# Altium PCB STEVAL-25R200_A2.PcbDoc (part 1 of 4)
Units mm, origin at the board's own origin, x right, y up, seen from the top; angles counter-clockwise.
Board outline 84.5 x 100 mm, 4 copper layers (Top Layer, F2, F3, Bottom Layer), stack 0.78 mm thick; 272 components, 152 nets, 679 pads, 380 vias.
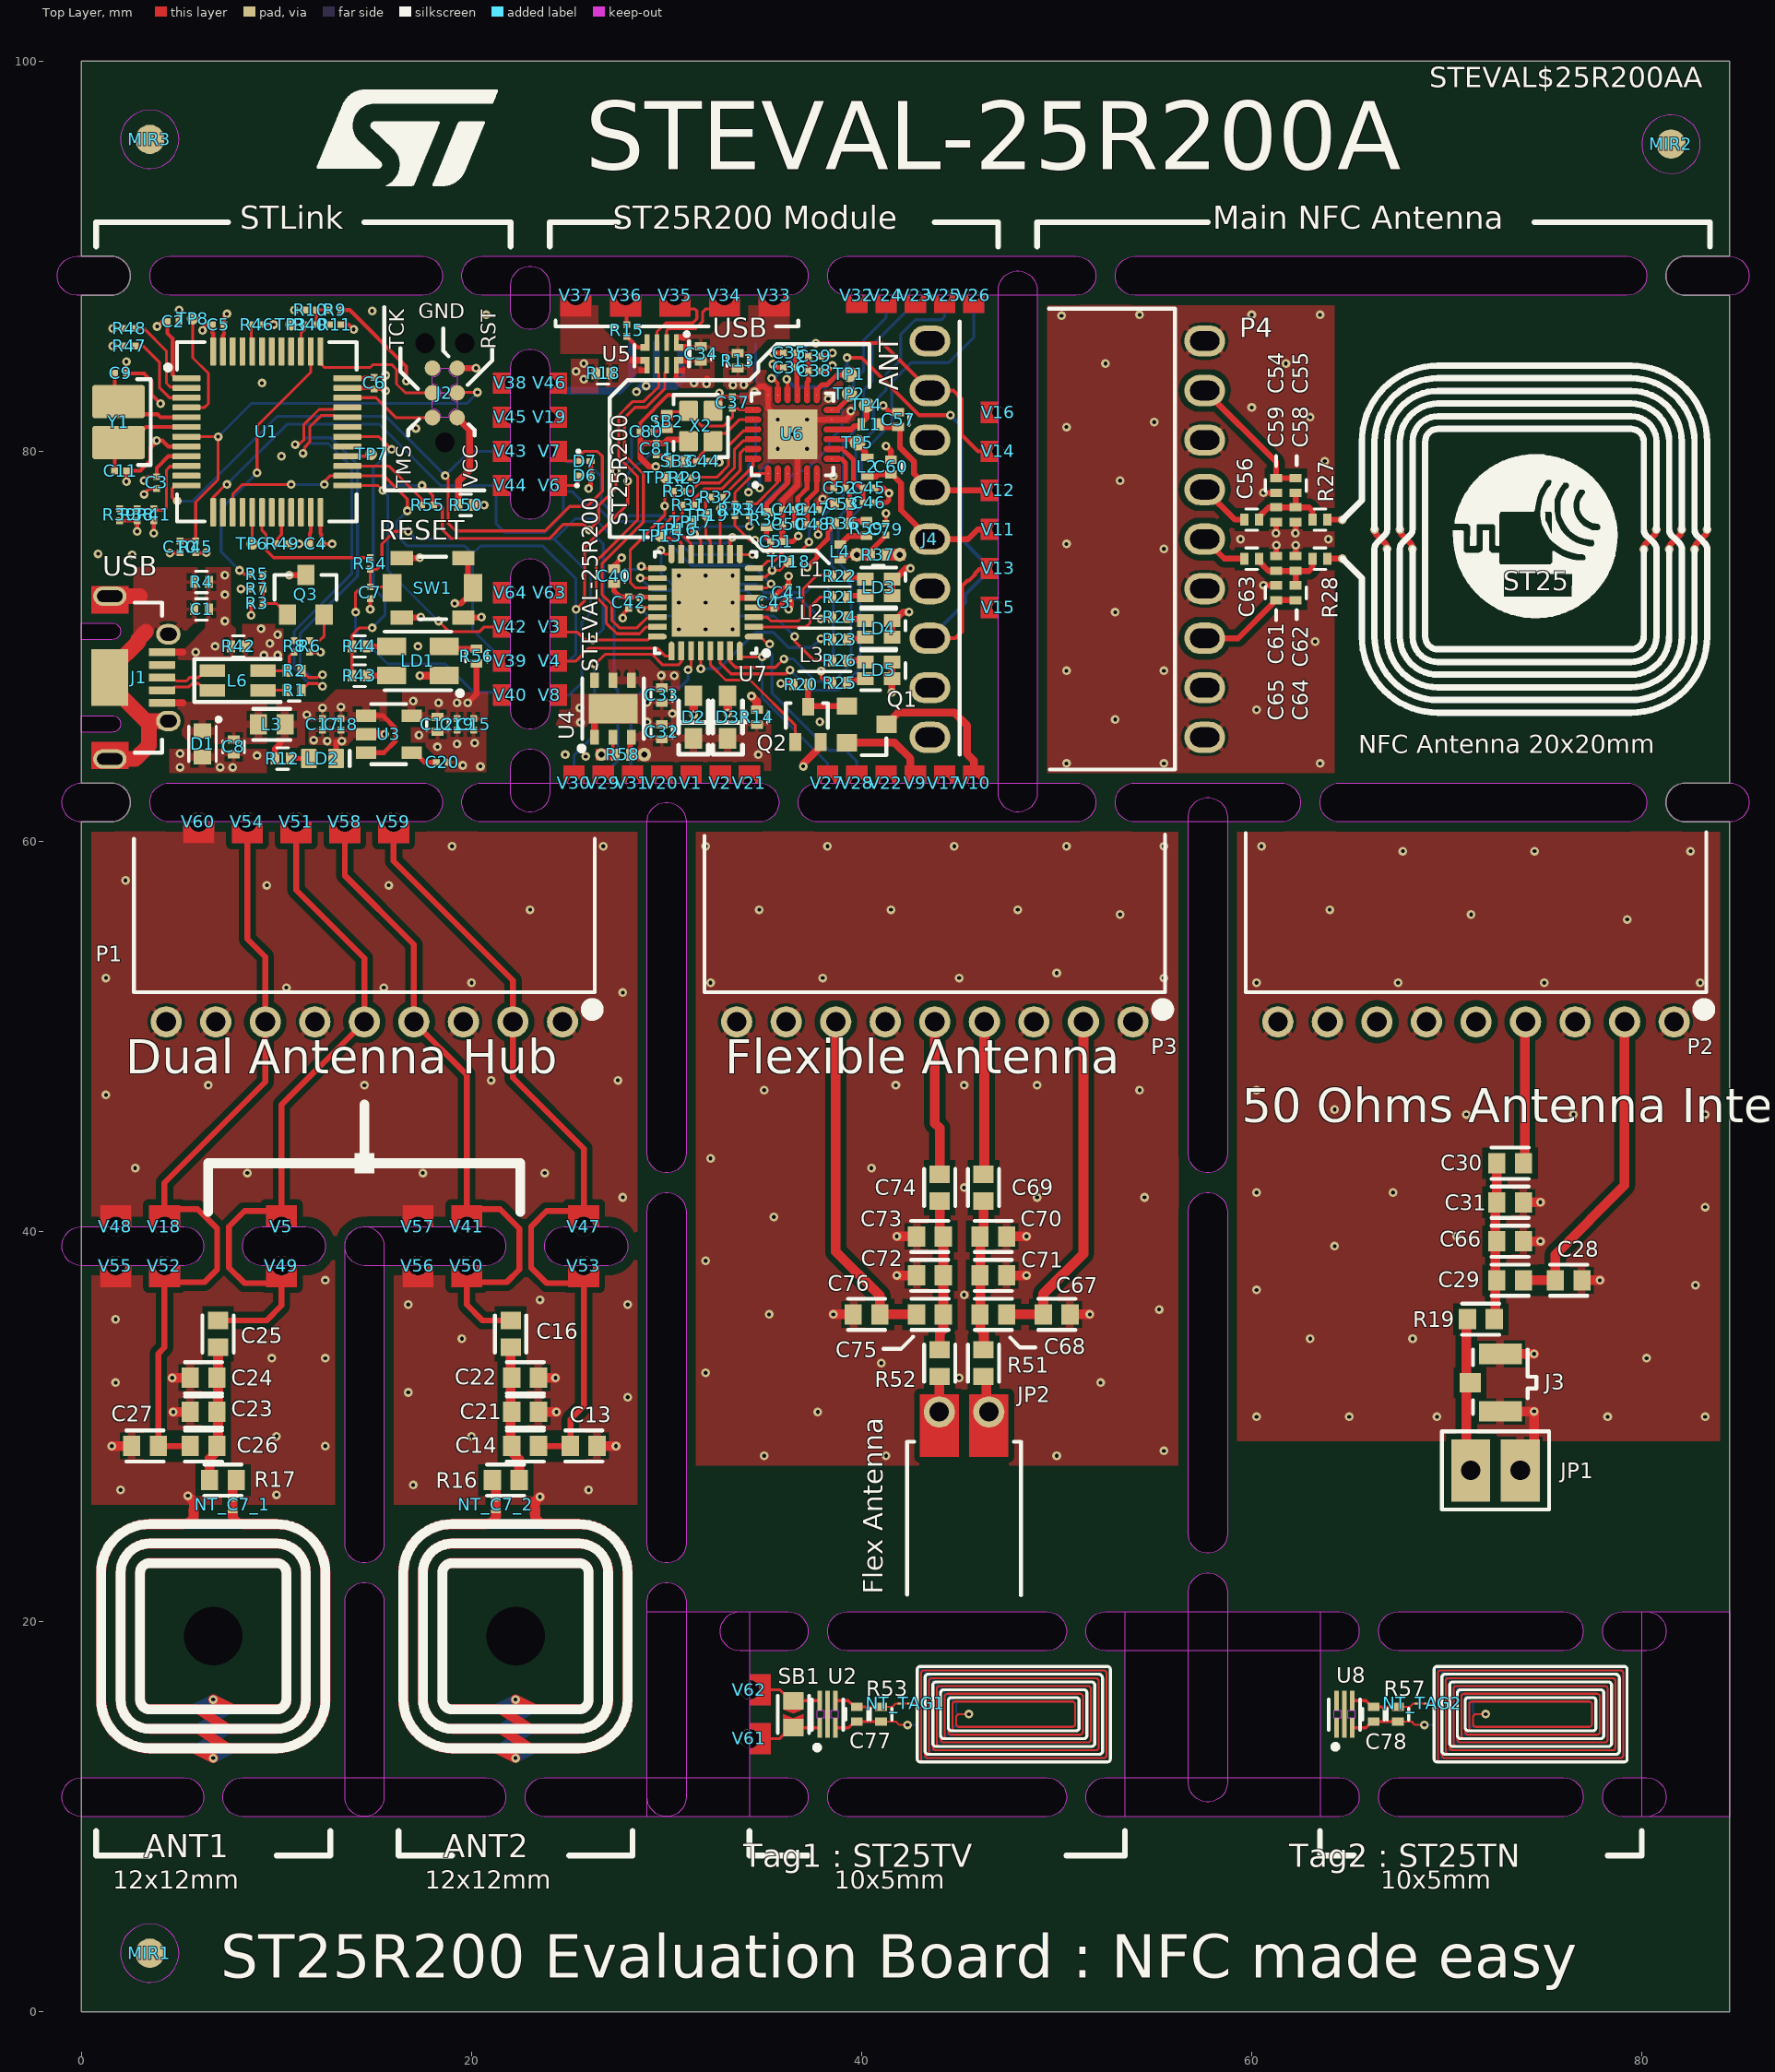
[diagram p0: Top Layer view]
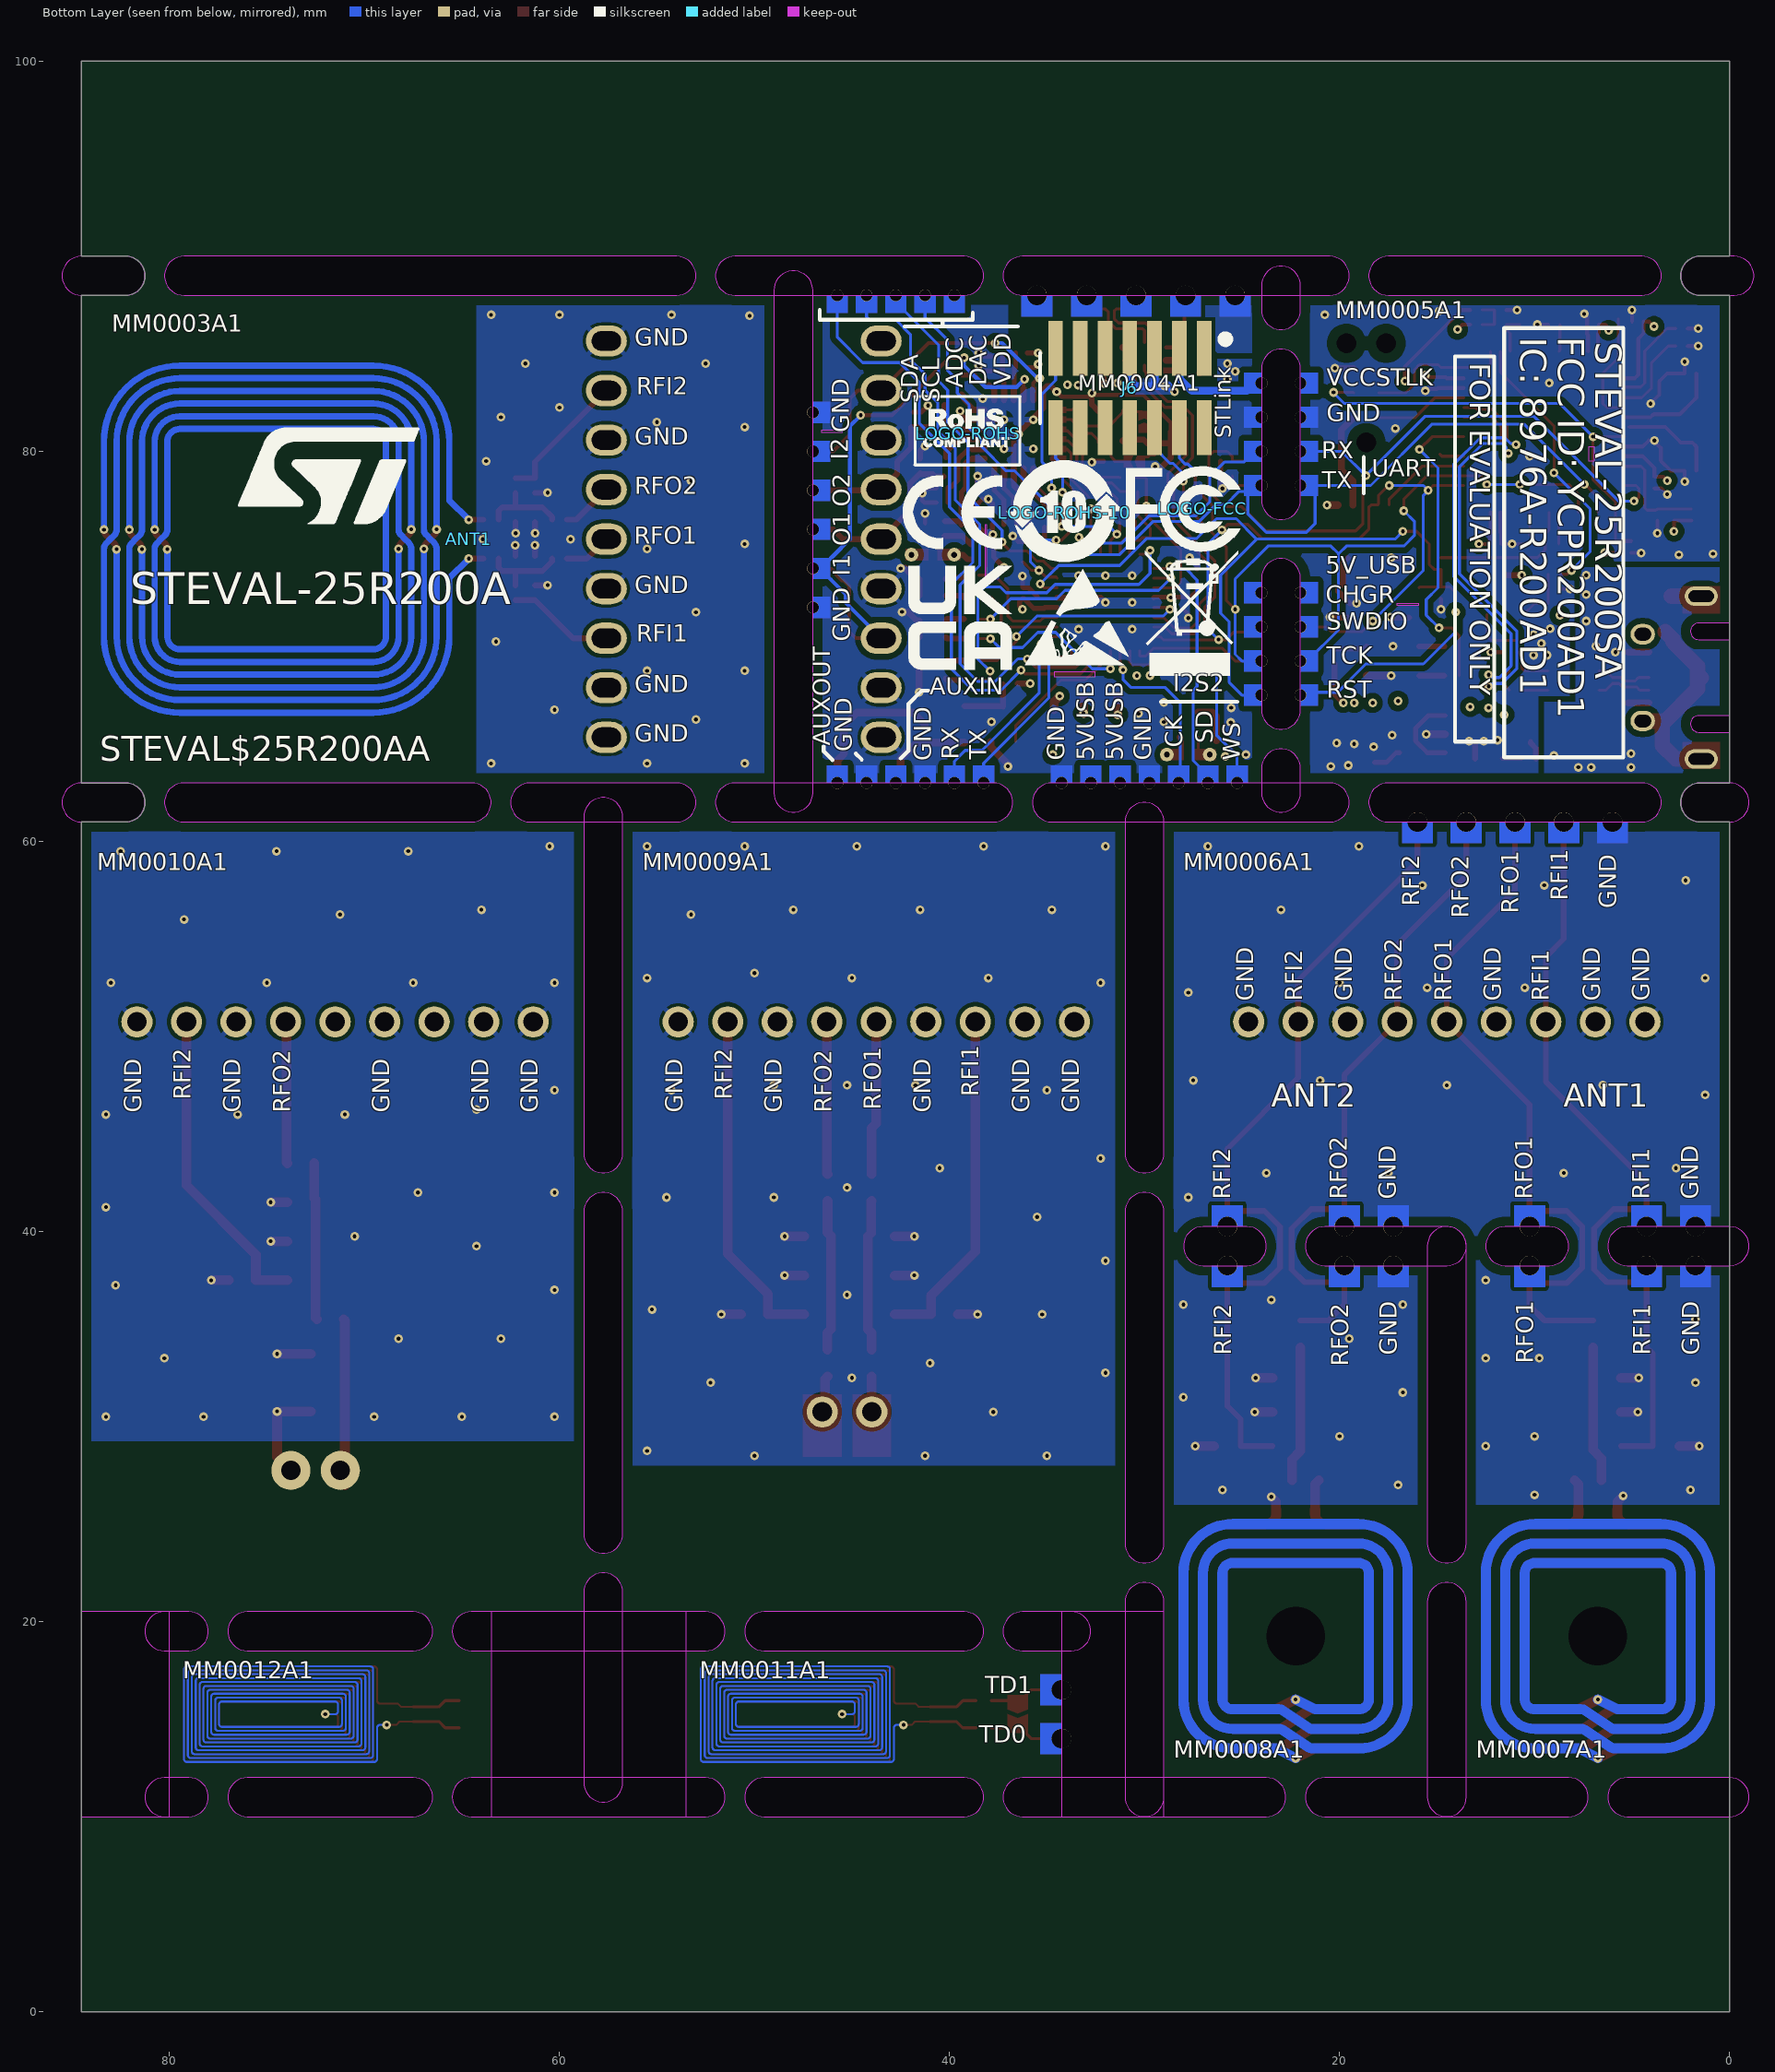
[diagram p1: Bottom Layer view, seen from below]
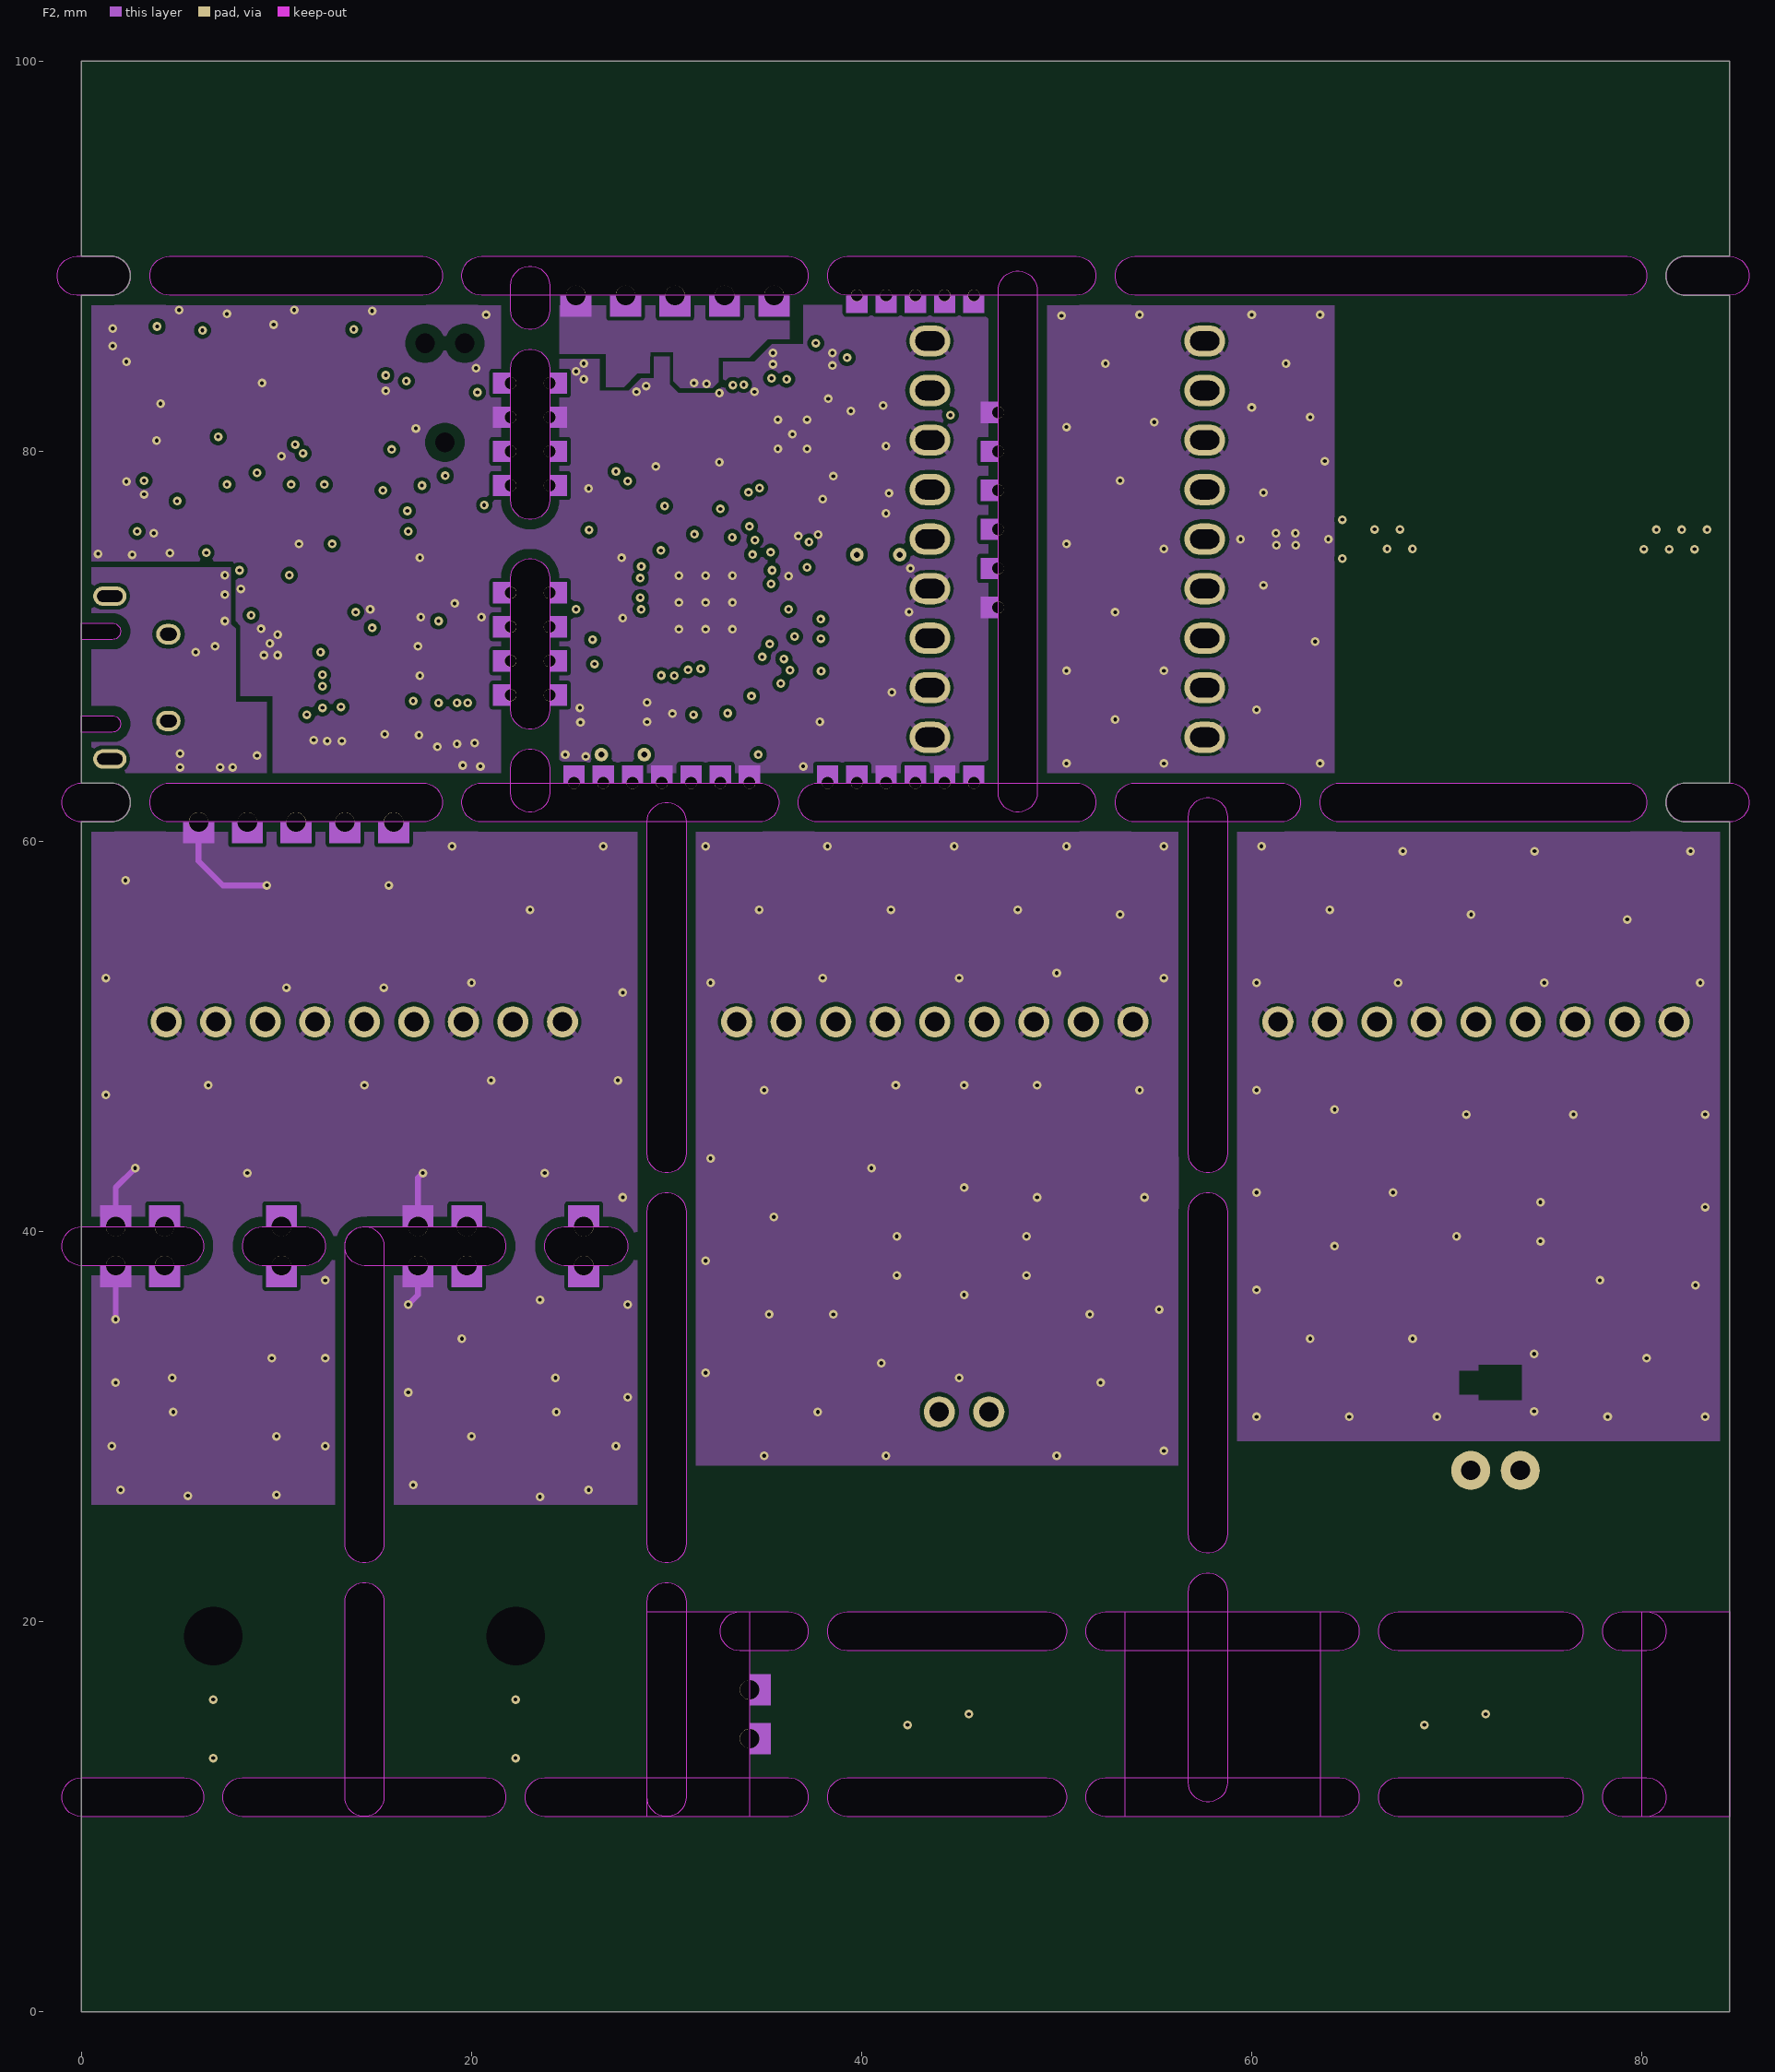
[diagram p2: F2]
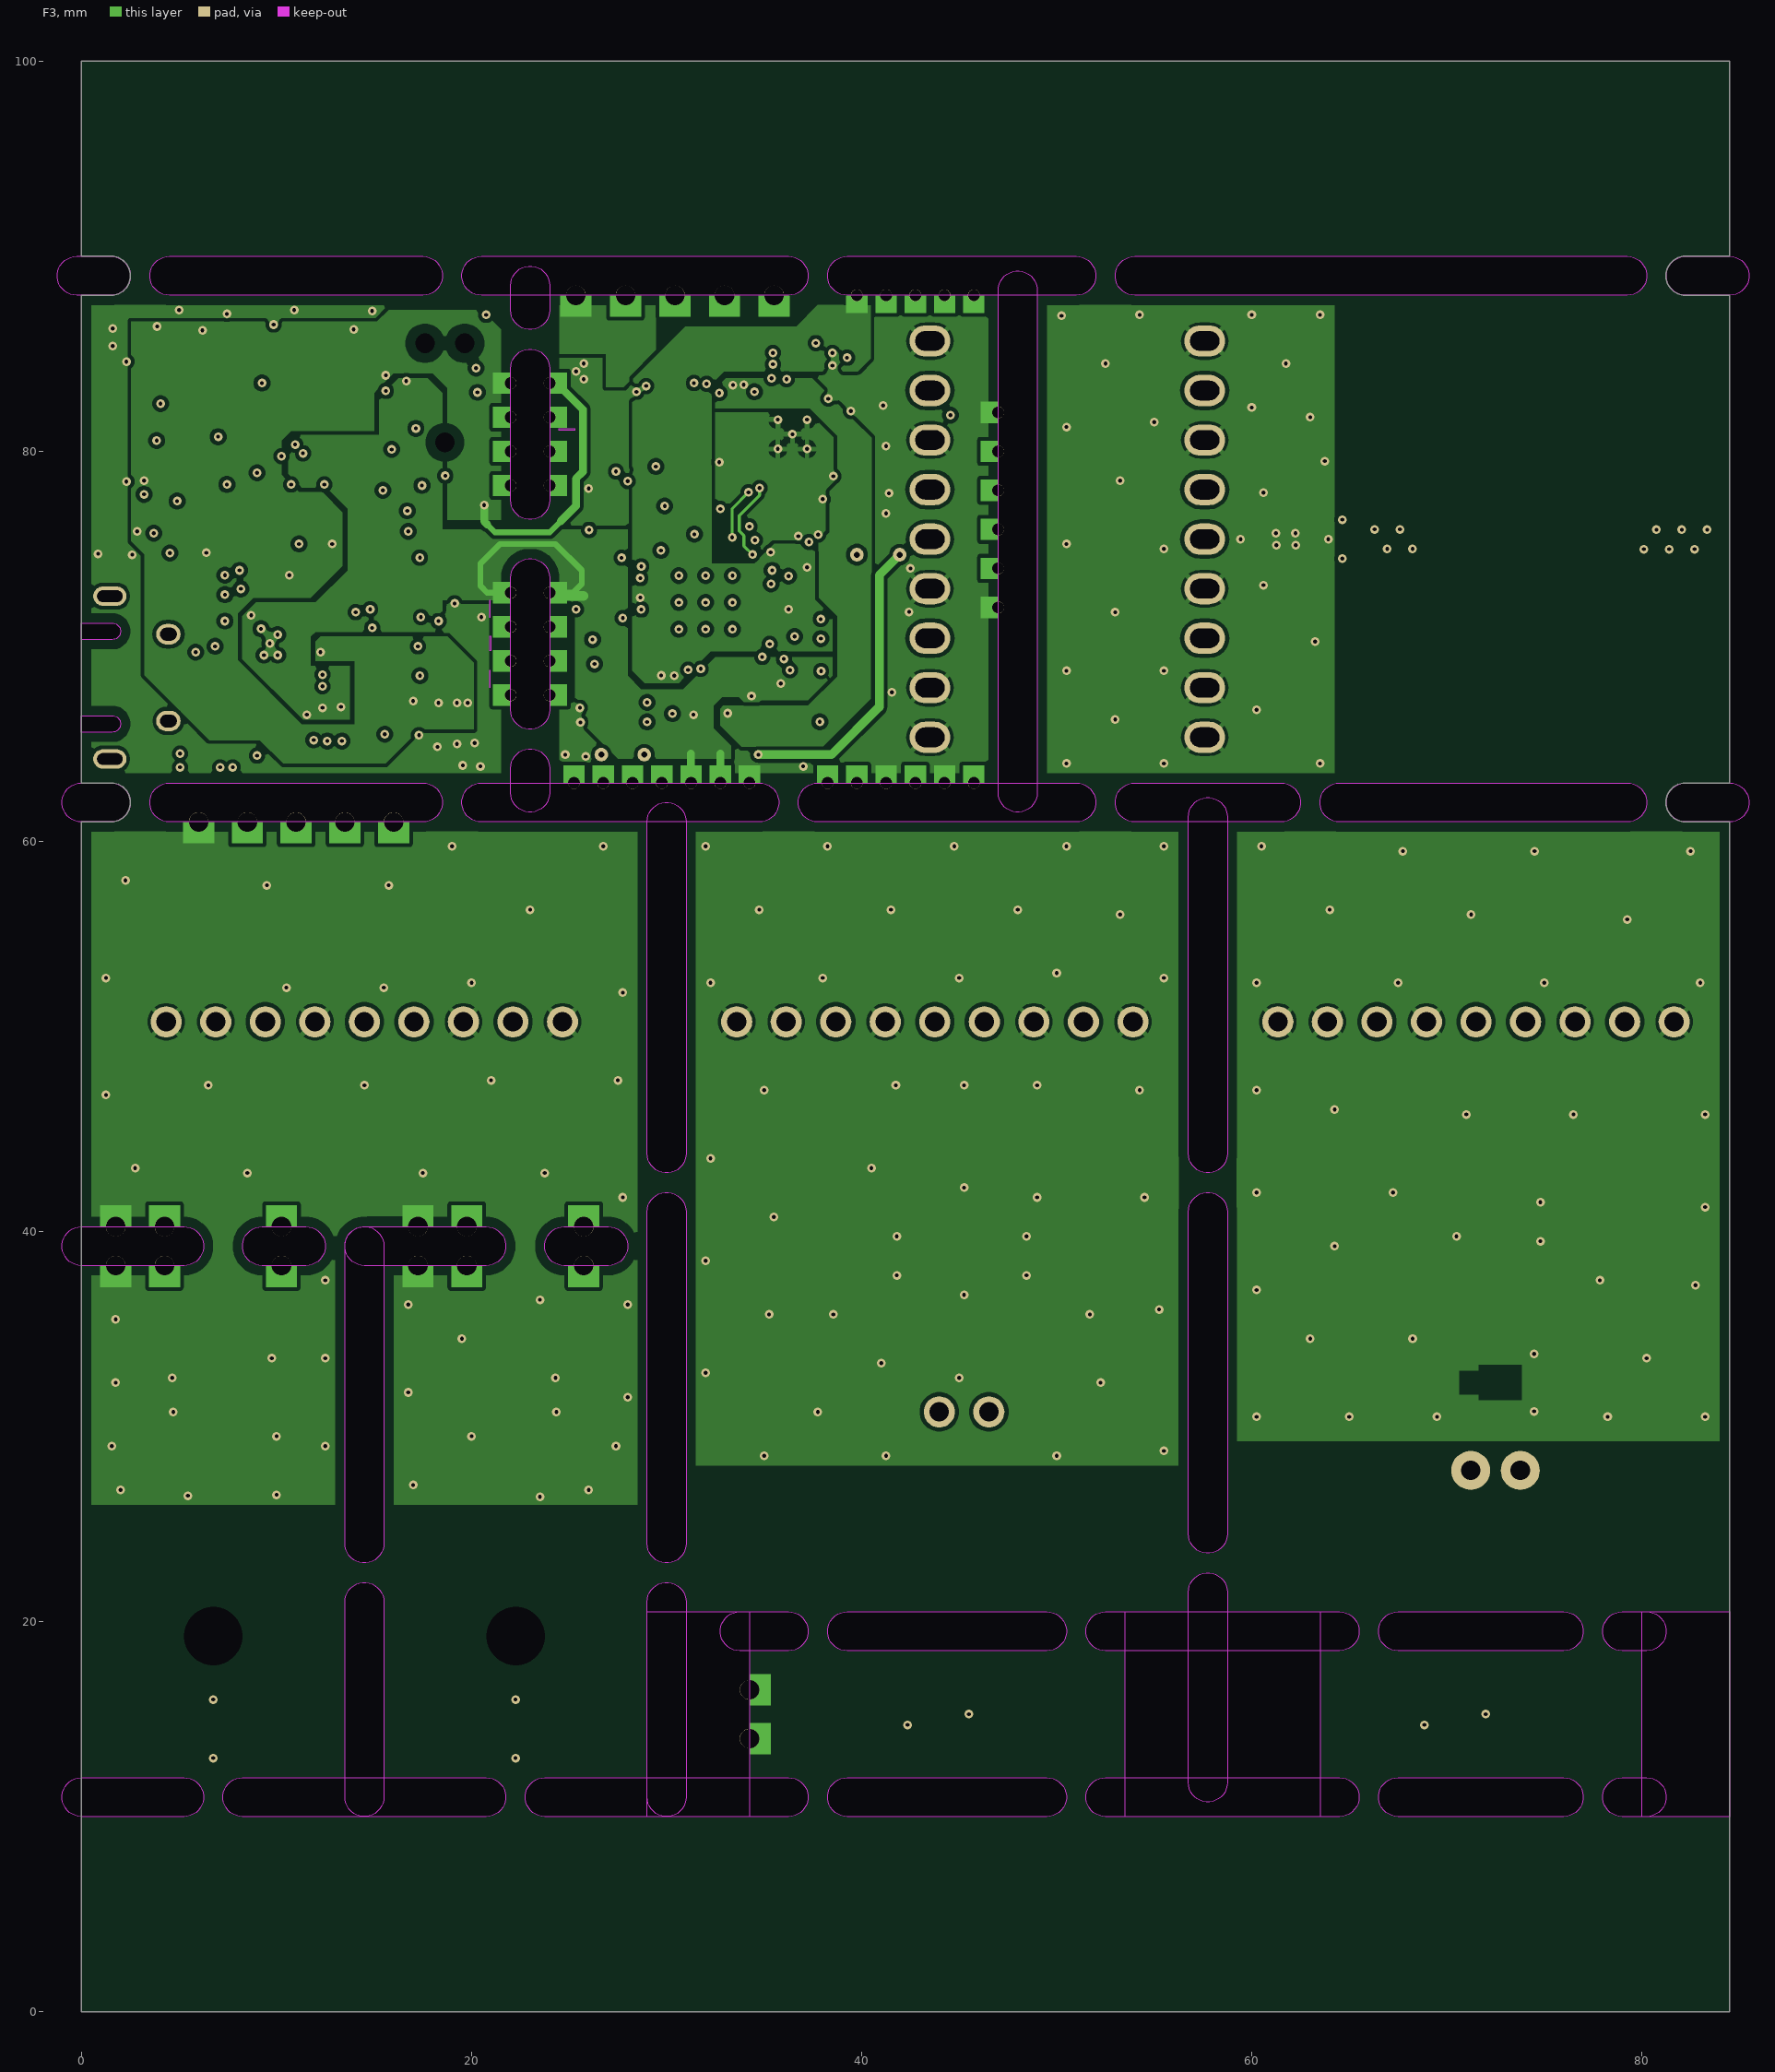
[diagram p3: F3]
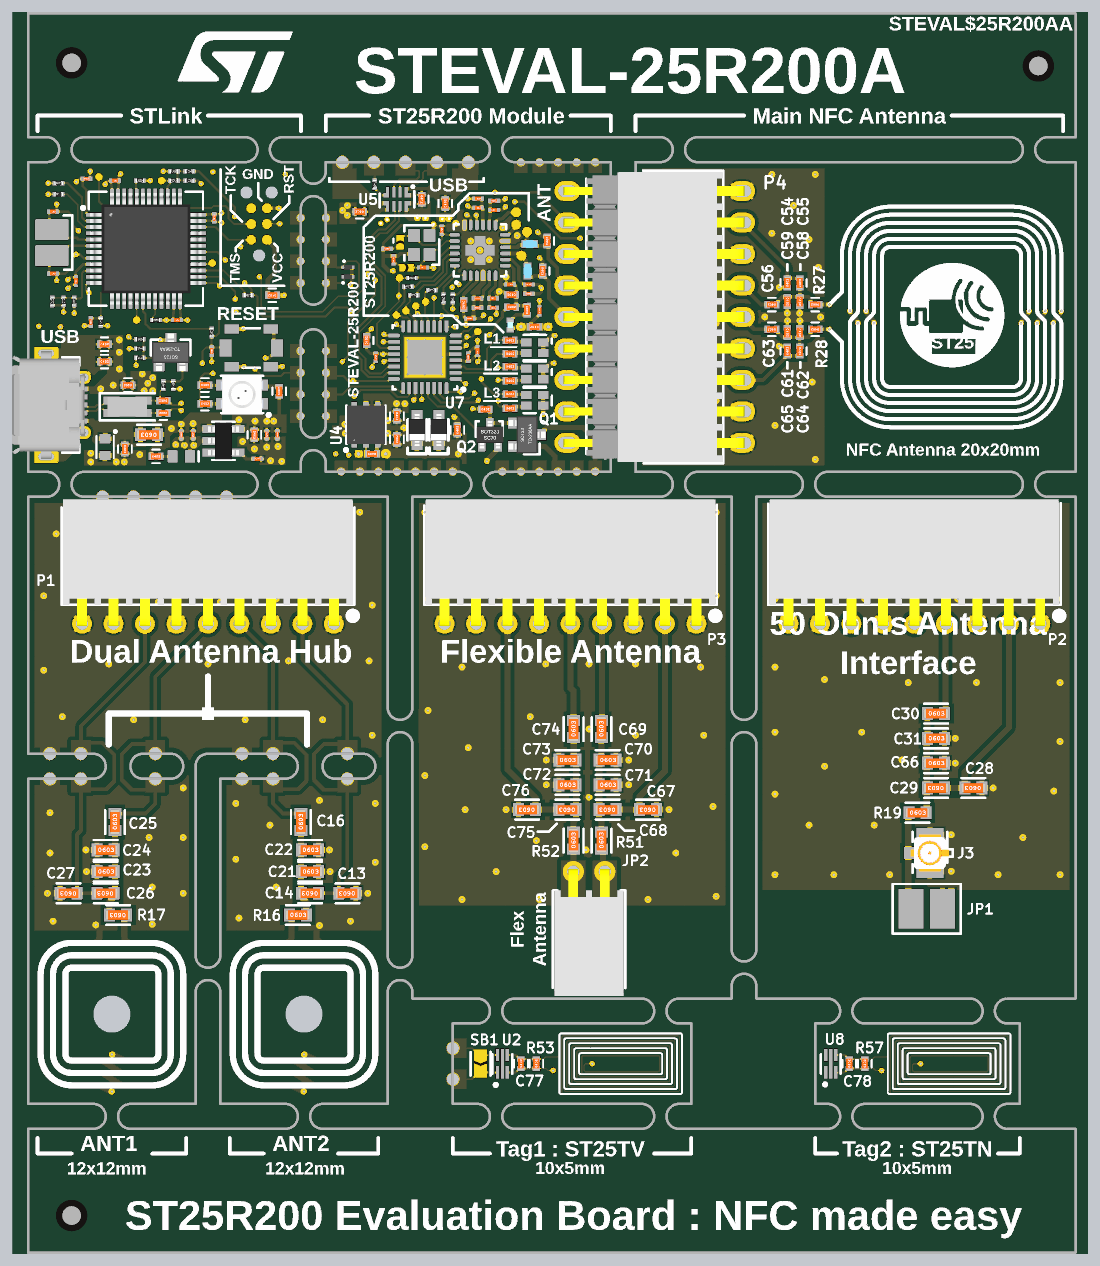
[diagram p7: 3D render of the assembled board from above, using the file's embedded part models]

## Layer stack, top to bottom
Top Solder: solder mask 0.02, Solder Resist, Dk 3.5
Top Layer: signal copper 0.035
Dielectric1: prepreg 0.12, FR-4, Dk 4.2
F2: signal copper 0.035
Dielectric2: core 0.4, FR-4, Dk 4.2
F3: signal copper 0.035
Dielectric3: prepreg 0.12, FR-4, Dk 4.2
Bottom Layer: signal copper 0.035
Bottom Solder: solder mask 0.02, Solder Resist, Dk 3.5

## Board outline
0,61 1.632,61 1.886,61.068 2.114,61.2 2.3,61.386 2.432,61.614 2.5,61.868 2.5,62.132 2.432,62.386 2.3,62.614 2.114,62.8 1.886,62.932 1.632,63 0,63 0,88 1.632,88 1.886,88.068 2.114,88.2 2.3,88.386 2.432,88.614 2.5,88.868 2.5,89.132 2.432,89.386 2.3,89.614 2.114,89.8 1.886,89.932 1.632,90 0,90 0,100 84.5,100 84.5,90 82.118,90 81.864,89.932 81.636,89.8 81.45,89.614 81.318,89.386 81.25,89.132 81.25,88.868 81.318,88.614 81.45,88.386 81.636,88.2 81.864,88.068 82.118,88 84.5,88 84.5,63 82.118,63 81.864,62.932 81.636,62.8 81.45,62.614 81.318,62.386 81.25,62.132 81.25,61.868 81.318,61.614 81.45,61.386 81.636,61.2 81.864,61.068 82.118,61 84.5,61 84.5,0 0,0
cut-out: 0,66.45 1.575,66.45 cw(c1.575,66.025) 1.575,65.6 0,65.6
cut-out: 0,71.2 1.575,71.2 cw(c1.575,70.775) 1.575,70.35 0,70.35
cut-out: 36.25,12 cw(c36.25,11) 36.25,10 23.75,10 cw(c23.75,11) 23.75,12
cut-out: 31,11 cw(c30,11) 29,11 29,21 cw(c30,21) 31,21
cut-out: 64.5,12 cw(c64.5,11) 64.5,10 52.5,10 cw(c52.5,11) 52.5,12
cut-out: 80.25,12 cw(c80.25,11) 80.25,10 79,10 cw(c79,11) 79,12
cut-out: 76,12 cw(c76,11) 76,10 67.5,10 cw(c67.5,11) 67.5,12
cut-out: 20.75,40.25 cw(c20.75,39.25) 20.75,38.25 14.5,38.25 cw(c14.5,39.25) 14.5,40.25
cut-out: 58.75,11.75 cw(c57.75,11.75) 56.75,11.75 56.75,21.5 cw(c57.75,21.5) 58.75,21.5
cut-out: 80.25,20.5 cw(c80.25,19.5) 80.25,18.5 79,18.5 cw(c79,19.5) 79,20.5
cut-out: 76,20.5 cw(c76,19.5) 76,18.5 67.5,18.5 cw(c67.5,19.5) 67.5,20.5
cut-out: 29,61 cw(c30,61) 31,61 31,44 cw(c30,44) 29,44
cut-out: 36.25,20.5 cw(c36.25,19.5) 36.25,18.5 33.75,18.5 cw(c33.75,19.5) 33.75,20.5
cut-out: 64.5,20.5 cw(c64.5,19.5) 64.5,18.5 52.5,18.5 cw(c52.5,19.5) 52.5,20.5
cut-out: 49.5,20.5 cw(c49.5,19.5) 49.5,18.5 39.25,18.5 cw(c39.25,19.5) 39.25,20.5
cut-out: 56.75,41 cw(c57.75,41) 58.75,41 58.75,24.5 cw(c57.75,24.5) 56.75,24.5
cut-out: 15.5,11 cw(c14.5,11) 13.5,11 13.5,21 cw(c14.5,21) 15.5,21
cut-out: 49.5,12 cw(c49.5,11) 49.5,10 39.25,10 cw(c39.25,11) 39.25,12
cut-out: 79.25,63 cw(c79.25,62) 79.25,61 64.5,61 cw(c64.5,62) 64.5,63
cut-out: 5.25,40.25 cw(c5.25,39.25) 5.25,38.25 0,38.25 cw(c0,39.25) 0,40.25
cut-out: 5.25,12 cw(c5.25,11) 5.25,10 0,10 cw(c0,11) 0,12
cut-out: 20.75,12 cw(c20.75,11) 20.75,10 8.25,10 cw(c8.25,11) 8.25,12
cut-out: 13.5,39.25 cw(c14.5,39.25) 15.5,39.25 15.5,24 cw(c14.5,24) 13.5,24
cut-out: 56.75,61.25 cw(c57.75,61.25) 58.75,61.25 58.75,44 cw(c57.75,44) 56.75,44
cut-out: 27,40.25 cw(c27,39.25) 27,38.25 24.75,38.25 cw(c24.75,39.25) 24.75,40.25
cut-out: 29,41 cw(c30,41) 31,41 31,24 cw(c30,24) 29,24
cut-out: 11.5,40.25 cw(c11.5,39.25) 11.5,38.25 9.25,38.25 cw(c9.25,39.25) 9.25,40.25
cut-out: 24,87.25 cw(c23,87.25) 22,87.25 22,88.5 cw(c23,88.5) 24,88.5
cut-out: 22,63.75 cw(c23,63.75) 24,63.75 24,62.5 cw(c23,62.5) 22,62.5
cut-out: 24,66.75 cw(c23,66.75) 22,66.75 22,73.5 cw(c23,73.5) 24,73.5
cut-out: 17.5,63 cw(c17.5,62) 17.5,61 4.5,61 cw(c4.5,62) 4.5,63
cut-out: 1.5,63 cw(c1.5,62) 1.5,61 0,61 cw(c0,62) 0,63
cut-out: 34.75,63 cw(c34.75,62) 34.75,61 20.5,61 cw(c20.5,62) 20.5,63
cut-out: 51,63 cw(c51,62) 51,61 37.75,61 cw(c37.75,62) 37.75,63
cut-out: 61.5,63 cw(c61.5,62) 61.5,61 54,61 cw(c54,62) 54,63
cut-out: 84.5,63 cw(c84.5,62) 84.5,61 82.25,61 cw(c82.25,62) 82.25,63
cut-out: 84.5,90 cw(c84.5,89) 84.5,88 82.25,88 cw(c82.25,89) 82.25,90
cut-out: 79.25,90 cw(c79.25,89) 79.25,88 54,88 cw(c54,89) 54,90
cut-out: 51,90 cw(c51,89) 51,88 39.25,88 cw(c39.25,89) 39.25,90
cut-out: 36.25,90 cw(c36.25,89) 36.25,88 20.5,88 cw(c20.5,89) 20.5,90
cut-out: 1.5,90 cw(c1.5,89) 1.5,88 -0.25,88 cw(c-0.25,89) -0.25,90
cut-out: 17.5,90 cw(c17.5,89) 17.5,88 4.5,88 cw(c4.5,89) 4.5,90
cut-out: 49,62.5 cw(c48,62.5) 47,62.5 47,88.25 cw(c48,88.25) 49,88.25
cut-out: 24,77.5 cw(c23,77.5) 22,77.5 22,84.25 cw(c23,84.25) 24,84.25
cut-out: 34.25,10 29,10 29,20.5 34.25,20.5
cut-out: 63.5,10 53.5,10 53.5,20.5 63.5,20.5
cut-out: 84.5,10 80,10 80,20.5 84.5,20.5

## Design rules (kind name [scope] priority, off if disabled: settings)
BoardOutlineClearance BoardClearance_TextIdentCouches [ISTEXT AND WithinRoom('TIDCouches')] p1: gap=0.5 ignorepadtopadclearanceinfootprint=FALSE except(0: Text-OutlineEdge)
BoardOutlineClearance BoardClearance_Castellations [InComponentClass('Castellations') or (istrack and (TouchesRoom('Castell') or TouchesRoom('Castell_1') or TouchesRoom('Castell_2') or TouchesRoom('Castell_3') or TouchesRoom('Castell_4') or TouchesRoom('Castell_5') or TouchesRoom('Castell_6') or TouchesRoom('Castell_7') or TouchesRoom('Castell_8') or TouchesRoom('Castell_9') or TouchesRoom('Castell_10') OR TouchesRoom('Castell_11')))] p2: gap=0 ignorepadtopadclearanceinfootprint=FALSE
BoardOutlineClearance BoardOutlineClearance_Serig [OnTopSilkscreen or OnBottomSilkscreen] p3: gap=0.2 ignorepadtopadclearanceinfootprint=FALSE
BoardOutlineClearance [not InComponentClass('Castellations')] p4: gap=0.5 ignorepadtopadclearanceinfootprint=FALSE
Clearance Clearance_Keepout [IsKeepOut] p1: gap=0.01 ignorepadtopadclearanceinfootprint=FALSE except(0: Arc-Hole Track-Hole SMDPad-Hole THPad-Hole Via-Hole Fill-Hole Poly-Hole Region-Hole Text-Hole)
Clearance Clearance-castellation-boardCutOut [InComponentClass('Castellations') or (istrack and (TouchesRoom('Castell') or TouchesRoom('Castell_1') or TouchesRoom('Castell_2') or TouchesRoom('Castell_3') or TouchesRoom('Castell_4') or TouchesRoom('Castell_5') or TouchesRoom('Castell_6') or TouchesRoom('Castell_7') or TouchesRoom('Castell_8') or TouchesRoom('Castell_9') or TouchesRoom('Castell_10') OR TouchesRoom('Castell_11'))) vs IsBoardCutoutRegion] p2: gap=0 ignorepadtopadclearanceinfootprint=FALSE
Clearance Clearance_NPTH_0.27 [IsSMTPin and InComponent('J2') vs ((ObjectKind = 'Pad') And (Layer = 'MultiLayer') And (PadIsPlated = 'False')) and InComponent('J2')] p3: gap=0.2 ignorepadtopadclearanceinfootprint=FALSE except(0.27: Arc-Hole Track-Hole SMDPad-Hole THPad-Hole Via-Hole Fill-Hole Poly-Hole Region-Hole Text-Hole; 0.3: Arc-Poly Track-Poly SMDPad-Poly THPad-Poly Via-Poly Fill-Poly Poly-Poly Poly-Region Poly-Text)
Clearance Clearance_NPTH [(ObjectKind = 'Pad') And (Layer = 'MultiLayer') And (PadIsPlated = 'False')] p4: gap=0.2 ignorepadtopadclearanceinfootprint=FALSE except(0.3: Arc-Poly Track-Poly SMDPad-Poly THPad-Poly Via-Poly Fill-Poly Poly-Poly Poly-Region Poly-Text; 0.5: Arc-Hole Track-Hole SMDPad-Hole THPad-Hole Via-Hole Fill-Hole Poly-Hole Region-Hole Text-Hole)
Clearance Clearance_Antenna_TAGS [WithinRoom('TAG1') or WithinRoom('TAG2') vs WithinRoom('TAG1') or WithinRoom('TAG2')] p5: gap=0.1 ignorepadtopadclearanceinfootprint=FALSE except(0: Arc-Hole Track-Hole SMDPad-Hole THPad-Hole Via-Hole Fill-Hole Poly-Hole Region-Hole Text-Hole)
Clearance Clearance-return-path-top [istrack and InAnyDifferentialPair and OnTopLayer vs IsVia and not InNetClass('Masses')] p6: gap=0.2 ignorepadtopadclearanceinfootprint=FALSE except(0: Arc-Hole Track-Hole SMDPad-Hole THPad-Hole Via-Hole Fill-Hole Poly-Hole Region-Hole Text-Hole; 0.15: Track-Track Via-Via; 0.175: Track-SMDPad)
Clearance Clearance-return-path-Bot [istrack and InAnyDifferentialPair and OnBottomLayer vs IsVia] p7: gap=0.2 ignorepadtopadclearanceinfootprint=FALSE except(0: Arc-Hole Track-Hole SMDPad-Hole THPad-Hole Via-Hole Fill-Hole Poly-Hole Region-Hole Text-Hole; 0.15: Track-Track Via-Via; 0.175: Track-SMDPad)
Clearance Clearance-POLY-st25r200 [InNamedPolygon('REMPLISSAGE-GND-ST25R200')] p8: gap=0.2 ignorepadtopadclearanceinfootprint=FALSE except(0: Arc-Hole Track-Hole SMDPad-Hole THPad-Hole Via-Hole Fill-Hole Poly-Hole Region-Hole Text-Hole; 0.125: Arc-Poly Track-Poly SMDPad-Poly THPad-Poly Via-Poly Fill-Poly Poly-Poly Poly-Region Poly-Text; 0.15: Track-Track Track-Via Via-Via; 0.175: Track-SMDPad)
Clearance Clearance-POLY-REMPL-GND-FC [InPolygonClass('REMPL-GND')] p9: gap=0.2 ignorepadtopadclearanceinfootprint=FALSE except(0: Arc-Hole Track-Hole SMDPad-Hole THPad-Hole Via-Hole Fill-Hole Poly-Hole Region-Hole Text-Hole; 0.15: Track-Track Track-Via Via-Via; 0.175: Track-SMDPad; 0.3: Arc-Poly Track-Poly SMDPad-Poly THPad-Poly Via-Poly Fill-Poly Poly-Poly Poly-Region Poly-Text)
Clearance Clearance_smd-smd-0.15 [HasFootprint('ST-ST0201') OR HasFootprint('ST-UFDFPN5-Pas=0.4-PKG-1.7x1.4') vs HasFootprint('ST-ST0201') OR HasFootprint('ST-UFDFPN5-Pas=0.4-PKG-1.7x1.4')] p10: gap=0.2 ignorepadtopadclearanceinfootprint=FALSE except(0: Arc-Hole Track-Hole SMDPad-Hole THPad-Hole Via-Hole Fill-Hole Poly-Hole Region-Hole Text-Hole; 0.15: Track-Track Track-Via SMDPad-SMDPad Via-Via; 0.3: Arc-Poly Track-Poly SMDPad-Poly THPad-Poly Via-Poly Fill-Poly Poly-Poly Poly-Region Poly-Text)
Clearance Clearance_track-smd-0.15 [IsSMTPin and InComponent('X2') vs IsTrack and InNet('XTI')] p11: gap=0.2 ignorepadtopadclearanceinfootprint=FALSE except(0: Arc-Hole Track-Hole SMDPad-Hole THPad-Hole Via-Hole Fill-Hole Poly-Hole Region-Hole Text-Hole; 0.15: Track-Track Track-SMDPad Track-Via Via-Via; 0.16: SMDPad-SMDPad; 0.3: Arc-Poly Track-Poly SMDPad-Poly THPad-Poly Via-Poly Fill-Poly Poly-Poly Poly-Region Poly-Text)
Clearance Clearance_Vias_SameNet [IsSMTPin and not InPadClass('THPADS') and not InComponent('ANT1') vs IsVia] p12: gap=0.2 ignorepadtopadclearanceinfootprint=FALSE except(0: Arc-Hole Track-Hole SMDPad-Hole THPad-Hole Via-Hole Fill-Hole Poly-Hole Region-Hole Text-Hole; 0.12: SMDPad-Via; 0.3: Arc-Poly Track-Poly SMDPad-Poly THPad-Poly Via-Poly Fill-Poly Poly-Poly Poly-Region Poly-Text)
Clearance Clearance-0.15 [All] p13: gap=0.2 ignorepadtopadclearanceinfootprint=FALSE except(0: Arc-Hole Track-Hole SMDPad-Hole THPad-Hole Via-Hole Fill-Hole Poly-Hole Region-Hole Text-Hole; 0.15: Track-Track Track-Via Via-Via; 0.175: Track-SMDPad)
ComponentClearance ComponentClearance_U2-SB1 [InComponent('SB1') vs InComponent('U2')] p1: gap=0 collisioncheckmode=3 verticalgap=0 showdistances=FALSE
ComponentClearance ComponentClearance_P1/SB1 [InComponent('P1')   OR InComponent('SB1') vs InComponentClass('Castellations')] p2: gap=0 collisioncheckmode=3 verticalgap=0 showdistances=FALSE
ComponentClearance ComponentClearance_J4 [InComponent('J4') vs InComponentClass('Castellations') or InComponent('p4')] p3: gap=0 collisioncheckmode=3 verticalgap=0 showdistances=FALSE
ComponentClearance ComponentClearance_P4 [InComponent('P4') vs InComponentClass('Castellations')] p4: gap=0 collisioncheckmode=3 verticalgap=0 showdistances=FALSE
ComponentClearance CompClearance_TagConnect [InComponent('J2') vs InComponent('V38') or InComponent('V43')   or InComponent('V44')  OR InComponent('V45')] p5: gap=0 collisioncheckmode=3 verticalgap=0 showdistances=FALSE
ComponentClearance [not InComponent('TP*') AND NOT InComponent('LOGO*') vs not InComponent('TP*') AND NOT InComponent('LOGO*')] p6: gap=0.24 collisioncheckmode=3 verticalgap=0.24 showdistances=FALSE
DiffPairsRouting [InAnyDifferentialPair] p1: maxlimit=0.15 minlimit=0.15 mostfreqgap=0.15 toplayer_minwidth=0.15 toplayer_maxwidth=0.15 toplayer_prefwidth=0.15 midlayer1_minwidth=0.15 midlayer1_maxwidth=0.15 midlayer1_prefwidth=0.15 midlayer2_minwidth=0.15 midlayer2_maxwidth=0.15 midlayer2_prefwidth=0.15 bottomlayer_minwidth=0.15 bottomlayer_maxwidth=0.15 bottomlayer_prefwidth=0.15 maxuncoupledlength=12.7
HoleSize [All] p1: absolutevalues=TRUE maxlimit=5 minlimit=0.2 maxpercent=80.000 minpercent=20.000
HoleToHoleClearance [All] p1: gap=0.35 allowstackedmicrovias=FALSE
MinimumAnnularRing MinimumAnnularRing-pad-0.175 [InPadClass('pad-with-annular-ring-0.175')] p1: minimumring=0.175
MinimumAnnularRing MinAnnularRing_vias-0.125 [IsVia] p2: minimumring=0.124
MinimumAnnularRing MinAnnularRing-0.2 [not InComponentClass('Castellations')] p3: minimumring=0.2
MinimumSolderMaskSliver MinimumSolderMaskSliver_inhibited [InPadClass('free-pads-associated-with-R58-R37') vs IsSMTPin and (InComponent('R58') or InComponent('R37'))] p1: minsoldermaskwidth=0.04
MinimumSolderMaskSliver [All] p2: minsoldermaskwidth=0.099
PermittedLayers PermittedLayers_LOGOS [InComponent('LOGO*')] p1: toplayerpermitted=TRUE bottomlayerpermitted=TRUE
PermittedLayers PermittedLayers_Bottom [InComponent('J6') or InComponent('ANT1')] p2: toplayerpermitted=FALSE bottomlayerpermitted=TRUE
PermittedLayers PermittedLayers_Top [All] p3: toplayerpermitted=TRUE bottomlayerpermitted=FALSE
PolygonConnect PolygonConnect_ST25R200 [InComponent('U6')] p1: thpad.connectstyle=Relief thpad.reliefconductorwidth=0.254 thpad.reliefentries=4 thpad.polygonreliefangle="90 Angle" thpad.airgapwidth=0.254 smdpad.connectstyle=Direct smdpad.reliefconductorwidth=0.3 smdpad.reliefentries=4 smdpad.polygonreliefangle="90 Angle" smdpad.airgapwidth=0.15 via.connectstyle=Relief via.reliefconductorwidth=0.254 via.reliefentries=4 via.polygonreliefangle="90 Angle" via.airgapwidth=0.254
PolygonConnect PolygonConnect_0402/0201 [HasFootprint('*0402*') or HasFootprint('*0201*')] p2: connectstyle=Relief reliefconductorwidth=0.2 reliefentries=4 polygonreliefangle="90 Angle" airgapwidth=0.15
PolygonConnect PolygonConnect_THPADS [InPadClass('THPADS') or InPadClass('noyees')] p3: connectstyle=Direct reliefconductorwidth=0.4 reliefentries=4 polygonreliefangle="45 Angle" airgapwidth=0.2
PolygonConnect [All] p4: thpad.connectstyle=Relief thpad.reliefconductorwidth=0.25 thpad.reliefentries=4 thpad.polygonreliefangle="45 Angle" thpad.airgapwidth=0.15 smdpad.connectstyle=Relief smdpad.reliefconductorwidth=0.4 smdpad.reliefentries=4 smdpad.polygonreliefangle="90 Angle" smdpad.airgapwidth=0.15 via.connectstyle=Direct via.reliefconductorwidth=0.254 via.reliefentries=4 via.polygonreliefangle="90 Angle" via.airgapwidth=0.254
ReturnPath ReturnPath-Diff [InAnyDifferentialPair and not WithinRoom('Castell_6')] p1: impedanceprofileid={6DDD52A1-DD19-4325-AFA8-EE845E1825B1} _gaplimit=0.02 _useantipads=TRUE
RoomDefinition TAG2 [False vs False] p1: confinementstyle=ConfineIn formatcopy=TRUE lockcomponents=FALSE outline 67,12.5 67,18 79.75,18 79.75,12.5
RoomDefinition TAG1 [False vs False] p2: confinementstyle=ConfineIn formatcopy=TRUE lockcomponents=FALSE outline 40.5,12.5 40.5,18 53.25,18 53.25,12.5
RoomDefinition Castell_11 [False vs False] p3: confinementstyle=ConfineIn formatcopy=TRUE lockcomponents=FALSE outline 32.672,12.6 32.672,17.5 35.75,17.5 35.75,12.6
RoomDefinition Castell_10 [False vs False] p4: confinementstyle=ConfineIn formatcopy=TRUE lockcomponents=FALSE outline 24.172,36.6 24.172,41.5 27.25,41.5 27.25,36.6
RoomDefinition Castell_9 [False vs False] p5: confinementstyle=ConfineIn formatcopy=TRUE lockcomponents=FALSE outline 8.922,36.85 8.922,41.75 21.5,41.75 21.5,36.85
RoomDefinition Castell_8 [False vs False] p6: confinementstyle=ConfineIn formatcopy=TRUE lockcomponents=FALSE outline -0.25,36.75 -0.25,41.65 6.25,41.65 6.25,36.75
RoomDefinition Castell_7 [False vs False] p7: confinementstyle=ConfineIn formatcopy=TRUE lockcomponents=FALSE outline 4.25,59.5 4.25,61.65 17.55,61.65 17.55,59.5
RoomDefinition Castell_5 [False vs False] p8: confinementstyle=ConfineIn formatcopy=TRUE lockcomponents=FALSE outline 39.2,87.1 39.2,88.35 46.5,88.35 46.5,87.1
RoomDefinition Castell_6 [False] p9: confinementstyle=ConfineIn formatcopy=TRUE lockcomponents=FALSE outline 24.55,86.9 24.55,88.8 36.3,88.8 36.3,86.9
RoomDefinition Castell_4 [False vs False] p10: confinementstyle=ConfineIn formatcopy=TRUE lockcomponents=FALSE outline 21.1,84.05 24.9,84.05 24.9,77.7 21.1,77.7
RoomDefinition Castell_3 [False vs False] p11: confinementstyle=ConfineIn formatcopy=TRUE lockcomponents=FALSE outline 21.1,73.3 24.9,73.3 24.9,66.95 21.1,66.95
RoomDefinition Castell_2 [False vs False] p12: confinementstyle=ConfineIn formatcopy=TRUE lockcomponents=FALSE outline 24.7,62.5 24.7,63.9 34.8,63.9 34.8,62.5
RoomDefinition Castell_1 [False vs False] p13: confinementstyle=ConfineIn formatcopy=TRUE lockcomponents=FALSE outline 37.7,62.5 37.7,63.9 46.3,63.9 46.3,62.5
RoomDefinition Castell [False vs False] p14: confinementstyle=ConfineIn formatcopy=TRUE lockcomponents=FALSE outline 46.1,82.75 47.5,82.75 47.5,70.75 46.1,70.75
RoomDefinition TIDCouches [False] p15: confinementstyle=ConfineIn formatcopy=TRUE lockcomponents=FALSE outline 5.25,113.5 83.5,113.5 83.5,101.5 5.25,101.5
RoutingLayers RoutingLayers_diff [InAnyDifferentialPair] p1: top layer_v5=TRUE mid layer 1_v5=FALSE mid layer 2_v5=FALSE bottom layer_v5=TRUE
RoutingLayers [All] p2: top layer_v5=TRUE mid layer 1_v5=TRUE mid layer 2_v5=TRUE bottom layer_v5=TRUE
RoutingVias [All] p1: holewidth=0.4 width=0.75 viastyle="Through Hole" minholewidth=0.4 minwidth=0.75 maxholewidth=0.4 maxwidth=0.75 useviatemplates=TRUE viatemplateguid#1={049F59BD-0977-481D-94F9-9B47A58CA45F} viatemplatename#1=via20-Pad=0.45
ShortCircuit ShortCircuit_Castellations [InComponentClass('Castellations') or (istrack and (TouchesRoom('Castell') or TouchesRoom('Castell_1') or TouchesRoom('Castell_2') or TouchesRoom('Castell_3') or TouchesRoom('Castell_4') or TouchesRoom('Castell_5') or TouchesRoom('Castell_6') or TouchesRoom('Castell_7') or TouchesRoom('Castell_8') or TouchesRoom('Castell_9') or TouchesRoom('Castell_10') OR TouchesRoom('Castell_11'))) vs IsBoardCutoutRegion] p1: allowed=TRUE
ShortCircuit [All] p2: allowed=FALSE
SilkToSilkClearance SilkClearance_LOGO-ST25 [InNamedUnion('LOGO-ST25') vs InNamedUnion('LOGO-ST25')] p1: silktosilkclearance=0
SilkToSilkClearance [All] p2: silktosilkclearance=0.1
SilkToSolderMaskClearance [IsPad or ((SolderMaskExpansionMode <> 'None') and not IsVia)] p1: minsilkscreentomaskgap=0.17 clearancetoexposedcopper=TRUE
SolderMaskExpansion SMExpansion_Vias-hole+0.05 [IsVia] p1: expansion=0.05 istentingtop=FALSE soldermaskfromhole=TRUE
SolderMaskExpansion SolderMaskExpansion_npth-0.15 [(ObjectKind = 'Pad') And (Layer = 'MultiLayer') And (PadIsPlated = 'False')] p2: expansion=0.15 istentingtop=FALSE soldermaskfromhole=TRUE
SolderMaskExpansion SolderMaskExpansion-0.025 [HasFootprint('ST-ST0201') OR HasFootprint('ST-UFDFPN5-Pas=0.4-PKG-1.7x1.4')] p3: expansion=0.025 istentingtop=FALSE
SolderMaskExpansion SolderMaskExpansion-0.05 [All] p4: expansion=0.05 istentingtop=FALSE
UnRoutedNet [All] p1: checkbadconnections=TRUE
ViasUnderSMD [InPadClass('THPADS') or InComponent('ANT1')] p1: allowed=TRUE
Width Width_TAGS [WithinRoom('TAG1') or WithinRoom('TAG2')] p1: maxlimit=0.254 minlimit=0.1 preferedwidth=0.254 toplayer_maxwidth=0.15 toplayer_prefwidth=0.15 midlayer1_minwidth=0.254 midlayer2_minwidth=0.254 bottomlayer_maxwidth=0.15 bottomlayer_prefwidth=0.15 minimp=50.000000 maximp=50.000000 favimp=50.000000
Width Width_Alims [InNetClass('Alims') or InNetClass('Masses')] p2: maxlimit=2 minlimit=0.19 preferedwidth=0.3 midlayer1_minwidth=0.2 midlayer2_minwidth=0.2 bottomlayer_minwidth=0.2 minimp=50.000000 maximp=50.000000 favimp=50.000000
Width [All] p3: maxlimit=2 minlimit=0.15 preferedwidth=0.15
20 further rules are at their usual default settings.

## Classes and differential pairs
pad class free-pads-associated-with-R58-R37: Free-1 Free-2 Free-3 Free-4
pad class pad-with-annular-ring-0.175: Free-1
polygon class REMPL-GND: rempl1-gnd-fc REMPL1-GND-FS rempl2-gnd-fc REMPL2-GND-FS rempl3-gnd-fc rempl4-gnd-fc
net class Masses: G0_GND_USB GND GND_50R GND_FLEX_ANT GND_HUB GND_USB NetC1_2
net class USB_STL: NetL6_2 NetL6_3 STL_USB_D_N STL_USB_D_P
net class USB_MCU: D_N D_P
net class CLK: NetC9_1 NetC11_1 STM_JTCK T_JTCK
pad class noyees: Free-1 Free-2 Free-3 Free-4
component class Castellations: V1 V2 V3 V4 V5 V6 V7 V8 V9 V10 V11 V12 V13 V14 V15 V16 V17 V18 V19 V20 V21 V22 V23 V24 V25 V26 V27 V28 V29 V30 V31 V32 V33 V34 V35 V36 V37 V38 V39 V40 V41 V42 V43 V44 V45 V46 V47 V48 V49 V50 V51 V52 V53 V54 V55 V56 V57 V58 V59 V60 V61 V62 V63 V64
net class USB: USB_IN_N USB_IN_P USB_N USB_P
net class Alims: 5V_USB_CHGR AGD G0_VBUS NetC8_2 NetC52_2 NetC79_2 NetJ2_1 NetL4_1 NetR35_2 V_USB VCC_STLK VDD_A VDD_AM VDD_D VDD_DR VDD_RF VDD_STM32
pad class THPADS: U4-7 U6-25 U7-33
differential pair D: +D_P -D_N
differential pair STL_USB_D: +STL_USB_D_P -STL_USB_D_N
differential pair USB: +USB_P -USB_N
differential pair USB_IN: +USB_IN_P -USB_IN_N

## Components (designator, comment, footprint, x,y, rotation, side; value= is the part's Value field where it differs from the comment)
ANT1 "ANTENNA-HW-R+T" ANTENNA-HWR+T 74.5,75.5 r0 bottom locked net-tie
C1 "4.7nF" 0402 6.15,71.9 r90 top
C2 "100nF" 0201-CAP 4.7,86.65 r0 top
C3 "100nF" 0201-CAP 3.85,78.4 r270 top
C4 "100nF" 0201-CAP 12,75.25 r0 top
C5 "100nF" 0201-CAP 7,86.5 r0 top
C6 "100nF" 0201-CAP 15,83.5 r270 top
C7 "100nF" 0201-CAP 14.8,72.75 r90 top
C8 "100pF" 0402 7.8,64.85 r0 top
C9 "10pF/25V" 0201-CAP 2,84 r0 top
C10 "100nF" 0201-CAP 5.05,75.1 r270 top
C11 "10pF/25V" 0201-CAP 2,79 r0 top
C12 "4.7uF/10V" 0402 18.25,66 r0 top
C13 "150pF" 0603 25.75,29 r270 top
C14 "10pF" 0603 22.75,29 r270 top
C15 "100nF" 0201-CAP 20.1,66 r90 top
C16 "39pF 2%" 0603 22,34.75 r180 top
C17 "1uF/10V" 0201-CAP 12.35,66 r90 top
C18 "100nF" 0201-CAP 13.3,66 r90 top
C19 "1uF/10V" 0201-CAP 19.25,66 r90 top
C20 "10nF" 0201-CAP 18.5,64.05 r180 top
C21 "220pF" 0603 22.75,30.75 r90 top
C22 "18pF 2%" 0603 22.75,32.5 r90 top
C23 "18pF 2%" 0603 6.25,30.75 r90 top
C24 "220pF" 0603 6.25,32.5 r90 top
C25 "39pF 2%" 0603 7,34.75 r180 top
C26 "10pF" 0603 6.25,29 r270 top
C27 "150pF" 0603 3.25,29 r270 top
C28 "150pF 2%" 0603 76.25,37.5 r270 top
C29 "10pF" 0603 73.25,37.5 r270 top
C30 "240pF 2%" 0603 73.25,43.5 r90 top
C31 "36pF 2%" 0603 73.25,41.5 r90 top
C32 "4.7uF/10V" 0402 29.75,65.625 r180 top
C33 "4.7uF/10V" 0402 29.75,67.5 r0 top
C34 "10uF/10V" 0402 31.75,85 r0 top
C35 "1uF/10V" 0201-CAP 36.3,85.05 r0 top
C36 "10nF" 0201-CAP 36.3,84.3 r0 top
C37 "10pF" 0201-CAP 33.375,82.5 r270 top
C38 "10nF" 0201-CAP 37.575,84.125 r180 top
C39 "2.2uF/10V" 0201-CAP 37.575,84.875 r180 top
C40 "4.7uF/10V" 0402 27.3,73.6 r180 top
C41 "100nF" 0201-CAP 36.25,72.75 r270 top
C42 "100nF" 0201-CAP 28.05,72.25 r270 top
C43 "100nF" 0201-CAP 35.5,72.25 r270 top
C44 "10pF" 0201-CAP 31.85,79.49 r180 top
C45 "10nF" 0201-CAP 40.375,78.125 r180 top
C46 "2.2uF/10V" 0201-CAP 40.375,77.375 r180 top
C47 "10nF" 0201-CAP 37.5,77 r180 top
C48 "2.2uF/10V" 0201-CAP 37.5,76.25 r180 top
C49 "10nF" 0201-CAP 36.25,77 r0 top
C50 "2.2uF/10V" 0201-CAP 36.25,76.25 r0 top
C51 "100nF" 0201-CAP 35.625,75.375 r180 top
C52 "10nF" 0201-CAP 38.875,78.125 r0 top
C53 "4.7uF/10V" 0402 39,77.3 r270 top
C54 "150pF 2%" 0402 61.25,78.25 r180 top
C55 "10pF" 0402 62.25,78.25 r0 top
C56 "36pF 2%" 0402 60,76.5 r270 top
C57 "240pF 2%" 0402 41.875,81.625 r180 top
C58 "240pF 2%" 0402 62.25,76.75 r0 top
C59 "22pF 2%" 0402 61.25,76.75 r0 top
C60 "240pF 2%" 0402 41.5,79.2 r0 top
C61 "22pF 2%" 0402 61.25,74.25 r0 top
C62 "240pF 2%" 0402 62.25,74.25 r0 top
C63 "36pF 2%" 0402 60,74.5 r270 top
C64 "10pF" 0402 62.25,72.75 r0 top
C65 "150pF 2%" 0402 61.25,72.75 r180 top
C66 "NC" 0603 73.25,39.5 r90 top
C67 "150pF 2%" 0603 50,35.75 r270 top
C68 "10pF" 0603 46.75,35.75 r270 top
C69 "39pF 2%" 0603 46.25,42.25 r180 top
C70 "330pF" 0603 46.75,39.75 r90 top
C71 "10pF" 0603 46.75,37.75 r90 top
C72 "10pF" 0603 43.5,37.75 r90 top
C73 "330pF" 0603 43.5,39.75 r90 top
C74 "39pF 2%" 0603 44,42.25 r180 top
C75 "10pF" 0603 43.5,35.75 r270 top
C76 "150pF 2%" 0603 40.25,35.75 r270 top
C77 "33pF" 0402 39.75,15.25 r180 top
C78 "6.8pF" 0402 66.25,15.25 r180 top
C79 "1uF/10V" 0201-CAP 41.25,76 r270 top
C80 "5.6pF" 0201-CAP 28.95,81.01 r0 top
C81 "5.6pF" 0201-CAP 29.47,80.12 r90 top
D1 "ESDA7P60-1U1M" ST-PACKAGE-1610-2PINS-A-K 6.2,65 r270 top
D2 "BAT60-NC" SOD323 31.375,66.375 r0 top
D3 "BAT60-NC" SOD323 33.125,66.375 r0 top
D6 "ESDALC6V1-1U2" ST-ST0201 25.8,78.75 r90 top
D7 "ESDALC6V1-1U2" ST-ST0201 25.8,79.5 r90 top
J1 "47590-0001" MOLEX-47590-0001 4.125,68.4 r270 top locked
J2 "TC2030-IDC-NL" TAG-CONNECT-FOOTPRINT-TC2030-IDC-NL 18.625,83 r90 top
J3 "RECE.20279.001E.01" TAOGLAS-RECE.20279.001E.01 72.75,32.25 r270 top
J4 "TSW-109-08-G-S-NA" SAMTEC-TSW-1X9PTS-NA-STYLE-08 43.5,75.5 r90 top locked
J6 "FTSH-107-01-L-DV-K NC" SAMTEC-FTSH-107-01-X-DV-K 30.75,83.25 r0 bottom
JP1 "SMD 2.0x3.2" PADS-x2-CMS-2.0x3.2-PAS-2.54 72.5,27.75 r180 top
JP2 "SSW-102-02-G-S-RA" SAMTEC-SSW-1X2PTS-RA-THROUGH-HOLE 45.25,30.75 r0 top
L1 "420nH" COILCRAFT-SELF-SERIE-0402DF 40.46,81.379 r0 top
L2 "420nH" COILCRAFT-SELF-SERIE-0402DF 40.3,79.2 r270 top
L3 "742792641" 0603 9.75,66 r270 top
L4 "BLM15PD121SN1D" 0402-SELF 38.9,74.85 r180 top
L6 "744232090" WURTH-WE-CNSW-1206 8,68.25 r90 top
LD1 "HSMF-A201-A00J1" LED-PACKAGE-PLCC-4 17.25,69.25 r0 top
LD2 "GREEN" EVERLIGHT-19-213 12.35,64.25 r180 top
LD3 "LTST-C195KGJRKT" LITE-ON-SMD-CHIP-LED-TOP-VIEW-BICOLOR-0606 40.875,73.025 r90 top
LD4 "LTST-C195KGJRKT" LITE-ON-SMD-CHIP-LED-TOP-VIEW-BICOLOR-0606 40.875,70.9 r90 top
LD5 "LTST-C195KGJRKT" LITE-ON-SMD-CHIP-LED-TOP-VIEW-BICOLOR-0606 40.875,68.775 r90 top
LOGO-FCC "Comment" "LOGO FCC" 27.05,77.05 r180 bottom
LOGO-ROHS "Comment" ST-ROHS-optimised 39.05,80.9 r180 bottom
LOGO-ROHS-10 "Comment" ST-ROHS-CHINOIS-10ans 34.1,76.85 r180 bottom
MIR1 "Fiducial" mire_optique_standard 3.5,3 r0 top
MIR2 "Fiducial" mire_optique_standard 81.5,95.75 r0 top
MIR3 "Fiducial" mire_optique_standard 3.5,96 r0 top
NT_C7_1 "Net-Tie-Width-0.50mm" Net-Tie-WIDTH-0.50mm 7.75,26 r0 top net-tie
NT_C7_2 "Net-Tie-Width-0.50mm" Net-Tie-WIDTH-0.50mm 21.25,26 r0 top net-tie
NT_TAG1 "Net-Tie-Width-0.10mm" Net-Tie-WIDTH-0.10mm 42.25,15.8 r270 top net-tie
NT_TAG2 "Net-Tie-Width-0.10mm" Net-Tie-WIDTH-0.10mm 68.75,15.8 r270 top net-tie
P1 "SSW-109-02-G-S-RA" SAMTEC-SSW-1X9PTS-RA-THROUGH-HOLE#1 14.5,50.75 r180 top
P2 "SSW-109-02-G-S-RA" SAMTEC-SSW-1X9PTS-RA-THROUGH-HOLE#1 71.5,50.75 r180 top
P3 "SSW-109-02-G-S-RA" SAMTEC-SSW-1X9PTS-RA-THROUGH-HOLE#1 43.75,50.75 r180 top
P4 "SSW-109-02-G-S-RA" SAMTEC-SSW-1X9PTS-RA-THROUGH-HOLE#2 57.59,75.5 r270 top locked
Q1 "STR2P3LLH6" SOT23-G-D-S 40.25,66 r90 top
Q2 "NHDTC114EU" SOT323-BCE 37.25,66 r180 top
Q3 "MMBT9013" SOT23-B-C-E 11.5,72.65 r180 top
R1 "10R" 0402 10.9,67.75 r270 top
R2 "10R" 0402 10.9,68.75 r270 top
R3 "10K" 0201-RES 9,72.2 r180 top
R4 "1M" 0402 6.15,73.3 r90 top
R5 "100R" 0201-RES 9,73.7 r180 top
R6 "NC" 0201-RES 11.7,70 r270 top
R7 "36K" 0201-RES 9,72.95 r0 top
R8 "1K5" 0201-RES 10.9,70 r90 top
R9 "2K7" 0201-RES 13,87.25 r180 top
R10 "4K7" 0201-RES 11.75,87.25 r180 top
R11 "0R NC" 0201-RES 13,86.5 r180 top
R12 "620R" 0402 10.3,64.25 r90 top
R13 "0R" 0402 33.65,84.65 r180 top
R14 "0R" 0402 34.625,66.375 r180 top
R15 "NC" 0201-RES 27.95,86.2 r270 top
R16 "1R5" 0603 21.75,27.25 r90 top
R17 "1R5" 0603 7.25,27.25 r270 top
R18 "0R" 0402 26.75,84 r270 top
R19 "1R5" 0603 71.75,35.5 r90 top
R20 "10K" 0402 36.88,68.05 r90 top
R21 "620R" 0402 38.875,72.525 r90 top
R22 "620R" 0402 38.875,73.605 r90 top
R23 "620R" 0402 38.875,70.35 r90 top
R24 "620R" 0402 38.875,71.5 r90 top
R25 "620R" 0402 38.875,68.125 r90 top
R26 "620R" 0402 38.875,69.275 r90 top
R27 "1R13" 0402 63.5,76.5 r270 top
R28 "1R13" 0402 63.5,74.5 r270 top
R29 "0R" 0201-RES 30.95,78.65 r0 top
R30 "0R" 0201-RES 30.65,77.95 r0 top
R31 "0R" 0201-RES 31.1,77.25 r0 top
R32 "0R" 0201-RES 32.55,77.65 r0 top
R33 "0R" 0201-RES 33.5,77 r90 top
R34 "0R" 0201-RES 34.25,77 r90 top
R35 "0R" 0402 35.125,76.5 r0 top
R36 "0R NC" 0402 39,76.3 r90 top
R37 "0R" 0402 40.85,74.7 r270 top
R38 "4K7" 0201-RES 2.85,76.75 r270 top
R39 "NC" 0201-RES 1.95,76.75 r270 top
R40 "0R" 0201-RES 11.75,86.5 r0 top
R41 "4K7" 0201-RES 3.7,76.75 r90 top
R42 "0R" 0402 8.05,70 r270 top
R43 "100R" 0402 14.25,68.5 r90 top
R44 "100R" 0402 14.25,70 r90 top
R45 "100K" 0201-RES 5.85,75.1 r270 top
R46 "100K" 0201-RES 9,86.5 r180 top
R47 "NC" 0201-RES 2.45,85.4 r0 top
R48 "10K" 0201-RES 2.45,86.3 r0 top
R49 "100K" 0201-RES 10.3,75.25 r180 top
R50 "0R" 0402 19.7,77.25 r270 top
R51 "560mR" 0603 46.25,33.25 r180 top
R52 "560mR" 0603 44,33.25 r180 top
R53 "TBD" 0402 41,15.25 r180 top
R54 "0R" 0201-RES 14.8,74.25 r90 top
R55 "100R" 0201-RES 17.75,77.25 r180 top
R56 "0R" 0402 20.25,69.5 r180 top
R57 "TBD" 0402 67.5,15.25 r180 top
R58 "0R" 0402 27.75,64.45 r270 top
R59 "0R" 0402 40.25,76.05 r180 top
SB1 "SB 0603" STRAP-FORMAT-0603-OUVERT 36.5,15.25 r180 top
SB2 "0402" STRAP-FORMAT-0402-OUVERT 30.01,81.53 r0 top
SB3 "0402" STRAP-FORMAT-0402-OUVERT 30.54,79.48 r270 top
SW1 "PTS820" C&K-INTER-SERIE-PTS820-WITHOUT-PEGS-H=2.0 18,73 r0 top
TP1 "SMD/0.8mm" PLAGE-CMS-DIAM-0.8mm 39.375,83.95 r180 top
TP2 "SMD/0.8mm" PLAGE-CMS-DIAM-0.8mm 39.375,82.95 r270 top
TP3 "SMD/0.6mm" PLAGE-CMS-DIAM-0.6mm 10.75,86.5 r180 top
TP4 "SMD/0.8mm" PLAGE-CMS-DIAM-0.8mm 40.25,82.375 r0 top
TP5 "SMD/0.8mm" PLAGE-CMS-DIAM-0.8mm 39.792,80.445 r0 top
TP6 "SMD/0.6mm" PLAGE-CMS-DIAM-0.6mm 8.75,75.25 r180 top
TP7 "SMD/0.6mm" PLAGE-CMS-DIAM-0.6mm 14.85,79.85 r180 top
TP8 "SMD/0.6mm" PLAGE-CMS-DIAM-0.6mm 5.7,86.8 r180 top
TP14 "SMD/0.6mm" PLAGE-CMS-DIAM-0.6mm 29.95,78.65 r90 top
TP15 "SMD/0.6mm" PLAGE-CMS-DIAM-0.6mm 29.7,75.65 r90 top
TP16 "SMD/0.6mm" PLAGE-CMS-DIAM-0.6mm 30.47,76 r90 top
TP17 "SMD/0.6mm" PLAGE-CMS-DIAM-0.6mm 31.27,76.38 r90 top
TP18 "SMD/0.6mm" PLAGE-CMS-DIAM-0.6mm 36.27,74.33 r90 top
TP19 "SMD/0.6mm" PLAGE-CMS-DIAM-0.6mm 32.06,76.73 r90 top
U1 "STM32F103CBT6" ST-LQFP48-PAS-0.5-7X7-H=1.6 9.5,81 r0 top locked
U2 "ST25TV02KC-TFH3" ST-UFDFPN5-Pas=0.4-PKG-1.7x1.4 38.25,15.25 r180 top
U3 "LD3985M33R" SOT23-5PINS 15.75,65.5 r90 top
U4 "LDO40LPU33RY" ST-DFN6-3X3 27.25,66.805 r0 top
U5 "ECMF02-4CMX8 NC" ST-MICRO-QFN-8L-PKG-2.5x1.2-PAS-0.5 29.75,85 r270 top
U6 "ST25R200" ST-QFN24-PAS0.5-4X4-THPAD-2.8MAX 36.45,80.875 r90 top
U7 "STM32G0B1KEU6N" ST-UFQFPN32-PAS-0.5-PKG-5X5X0.55 32,72.25 r180 top
U8 "ST25TN01KAFH5" ST-UFDFPN5-Pas=0.4-PKG-1.7x1.4 64.75,15.25 r180 top
V1 "CASTELLATION" CASTELLATED_VIA_DRILL=0.6-PAD=1.1 31.25,63 r90 top locked
V2 "CASTELLATION" CASTELLATED_VIA_DRILL=0.6-PAD=1.1 32.75,63 r90 top locked
V3 "CASTELLATION" CASTELLATED_VIA_DRILL=0.6-PAD=1.1 24,71 r0 top locked
V4 "CASTELLATION" CASTELLATED_VIA_DRILL=0.6-PAD=1.1 24,69.25 r0 top locked
V5 "CASTELLATION" CASTELLATED_VIA 10.25,40.25 r90 top locked
V6 "CASTELLATION" CASTELLATED_VIA_DRILL=0.6-PAD=1.1 24,78.25 r0 top locked
V7 "CASTELLATION" CASTELLATED_VIA_DRILL=0.6-PAD=1.1 24,80 r0 top locked
V8 "CASTELLATION" CASTELLATED_VIA_DRILL=0.6-PAD=1.1 24,67.5 r0 top locked
V9 "CASTELLATION" CASTELLATED_VIA_DRILL=0.6-PAD=1.1 42.75,63 r90 top locked
V10 "CASTELLATION" CASTELLATED_VIA_DRILL=0.6-PAD=1.1 45.75,63 r90 top locked
V11 "CASTELLATION" CASTELLATED_VIA_DRILL=0.6-PAD=1.1 47,76 r180 top locked
V12 "CASTELLATION" CASTELLATED_VIA_DRILL=0.6-PAD=1.1 47,78 r180 top locked
V13 "CASTELLATION" CASTELLATED_VIA_DRILL=0.6-PAD=1.1 47,74 r180 top locked
V14 "CASTELLATION" CASTELLATED_VIA_DRILL=0.6-PAD=1.1 47,80 r180 top locked
V15 "CASTELLATION" CASTELLATED_VIA_DRILL=0.6-PAD=1.1 47,72 r180 top locked
V16 "CASTELLATION" CASTELLATED_VIA_DRILL=0.6-PAD=1.1 47,82 r180 top locked
V17 "CASTELLATION" CASTELLATED_VIA_DRILL=0.6-PAD=1.1 44.25,63 r90 top locked
V18 "CASTELLATION" CASTELLATED_VIA 4.25,40.25 r90 top locked
V19 "CASTELLATION" CASTELLATED_VIA_DRILL=0.6-PAD=1.1 24,81.75 r0 top locked
V20 "CASTELLATION" CASTELLATED_VIA_DRILL=0.6-PAD=1.1 29.75,63 r90 top locked
V21 "CASTELLATION" CASTELLATED_VIA_DRILL=0.6-PAD=1.1 34.25,63 r90 top locked
V22 "CASTELLATION" CASTELLATED_VIA_DRILL=0.6-PAD=1.1 41.25,63 r90 top locked
V23 "CASTELLATION" CASTELLATED_VIA_DRILL=0.6-PAD=1.1 42.75,88 r270 top locked
V24 "CASTELLATION" CASTELLATED_VIA_DRILL=0.6-PAD=1.1 41.25,88 r270 top locked
V25 "CASTELLATION" CASTELLATED_VIA_DRILL=0.6-PAD=1.1 44.25,88 r270 top locked
V26 "CASTELLATION" CASTELLATED_VIA_DRILL=0.6-PAD=1.1 45.75,88 r270 top locked
V27 "CASTELLATION" CASTELLATED_VIA_DRILL=0.6-PAD=1.1 38.25,63 r90 top locked
V28 "CASTELLATION" CASTELLATED_VIA_DRILL=0.6-PAD=1.1 39.75,63 r90 top locked
V29 "CASTELLATION" CASTELLATED_VIA_DRILL=0.6-PAD=1.1 26.75,63 r90 top locked
V30 "CASTELLATION" CASTELLATED_VIA_DRILL=0.6-PAD=1.1 25.25,63 r90 top locked
V31 "CASTELLATION" CASTELLATED_VIA_DRILL=0.6-PAD=1.1 28.25,63 r90 top locked
V32 "CASTELLATION" CASTELLATED_VIA_DRILL=0.6-PAD=1.1 39.75,88 r270 top locked
V33 "CASTELLATION" CASTELLATED_VIA 35.51,88 r270 top locked
V34 "CASTELLATION" CASTELLATED_VIA 32.97,88 r270 top locked
V35 "CASTELLATION" CASTELLATED_VIA 30.43,88 r270 top locked
V36 "CASTELLATION" CASTELLATED_VIA 27.89,88 r270 top locked
V37 "CASTELLATION" CASTELLATED_VIA 25.35,88 r270 top locked
V38 "CASTELLATION" CASTELLATED_VIA_DRILL=0.6-PAD=1.1 22,83.5 r180 top locked
V39 "CASTELLATION" CASTELLATED_VIA_DRILL=0.6-PAD=1.1 22,69.25 r180 top locked
V40 "CASTELLATION" CASTELLATED_VIA_DRILL=0.6-PAD=1.1 22,67.5 r180 top locked
V41 "CASTELLATION" CASTELLATED_VIA 19.75,40.25 r90 top locked
V42 "CASTELLATION" CASTELLATED_VIA_DRILL=0.6-PAD=1.1 22,71 r180 top locked
V43 "CASTELLATION" CASTELLATED_VIA_DRILL=0.6-PAD=1.1 22,80 r180 top locked
V44 "CASTELLATION" CASTELLATED_VIA_DRILL=0.6-PAD=1.1 22,78.25 r180 top locked
V45 "CASTELLATION" CASTELLATED_VIA_DRILL=0.6-PAD=1.1 22,81.75 r180 top locked
V46 "CASTELLATION" CASTELLATED_VIA_DRILL=0.6-PAD=1.1 24,83.5 r0 top locked
V47 "CASTELLATION" CASTELLATED_VIA 25.75,40.25 r90 top locked
V48 "CASTELLATION" CASTELLATED_VIA 1.75,40.25 r90 top locked
V49 "CASTELLATION" CASTELLATED_VIA 10.25,38.25 r270 top locked
V50 "CASTELLATION" CASTELLATED_VIA 19.75,38.25 r270 top locked
V51 "CASTELLATION" CASTELLATED_VIA 11,61 r270 top locked
V52 "CASTELLATION" CASTELLATED_VIA 4.25,38.25 r270 top locked
V53 "CASTELLATION" CASTELLATED_VIA 25.75,38.25 r270 top locked
V54 "CASTELLATION" CASTELLATED_VIA 8.5,61 r270 top locked
V55 "CASTELLATION" CASTELLATED_VIA 1.75,38.25 r270 top locked
V56 "CASTELLATION" CASTELLATED_VIA 17.25,38.25 r270 top locked
V57 "CASTELLATION" CASTELLATED_VIA 17.25,40.25 r90 top locked
V58 "CASTELLATION" CASTELLATED_VIA 13.5,61 r270 top locked
V59 "CASTELLATION" CASTELLATED_VIA 16,61 r270 top locked
V60 "CASTELLATION" CASTELLATED_VIA 6,61 r270 top locked
V61 "CASTELLATION" CASTELLATED_VIA 34.25,14 r0 top locked
V62 "CASTELLATION" CASTELLATED_VIA 34.25,16.5 r0 top locked
V63 "CASTELLATION" CASTELLATED_VIA_Drill=0.6-Pad=1.1 24,72.75 r0 top locked
V64 "CASTELLATION" CASTELLATED_VIA_Drill=0.6-Pad=1.1 22,72.75 r180 top locked
X2 "NX2016SA 27.12MHz" NDK-NX2016SA 31.75,81.3 r180 top
Y1 "NX3225GD-8MHZ" NDK-NX3225GD 1.9,81.5 r90 top

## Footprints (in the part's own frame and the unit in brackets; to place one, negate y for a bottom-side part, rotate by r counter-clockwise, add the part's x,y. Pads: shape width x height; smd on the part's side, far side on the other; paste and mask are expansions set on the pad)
0201-CAP [mm]
  rect 0.35x0.35 smd: 1(-0.3,0) 2(0.3,0)
  body extent -0.31,-0.15 0.3,0.15, height 0.31
0201-RES [mm]
  rect 0.35x0.35 smd: 1(-0.3,0) 2(0.3,0)
  body extent -0.34,-0.17 0.34,0.16, height 0.34
0402 [mil]
  rect 24x17 smd: 1(0,-15) 2(0,15)
  silkscreen extent -22,-12 22,12, body extent -10,-20 10,20, height 20
0402-SELF [mil]
  rect 24x17 smd: 1(0,-15) 2(0,15)
  body extent -10,-20 10,20, height 20
0603 [mil]
  rect 41x35 smd: 1(0,-27) 2(0,27)
  silkscreen extent -31,-37 31,38, body extent -15,-39 16,39, height 31
ANTENNA-HWR+T [mm] "66mm x 66mm"
  round 0.325 smd paste-1 mask-1: 1(-9.854,1) 2(-9.854,-1)
  Top Layer lines w0.325: -9.854,1 -8.854,2 -8.854,4.999 cw(c-4.954,4.999) -4.954,8.899 ; -9.854,-1 -8.854,-2 -8.854,-4.999 ccw(c-4.954,-4.999) -4.954,-8.899 ; -8.204,5.014 -8.204,0.5 ccw(c-7.766,0.5) -8.076,0.19 -7.871,-0.015 -7.673,-0.212 cw(c-7.961,-0.5) -7.554,-0.5 -7.554,-5.013 ; -8.204,4.999 cw(c-4.954,4.999) -4.954,8.249 ; -8.204,-0.5 -8.204,-5.014 ; -8.204,-4.999 ccw(c-4.954,-4.999) -4.954,-8.249 ; -7.554,5.013 -7.554,0.5 ; -7.554,5 cw(c-4.954,5) -4.954,7.6 ; -7.554,-5 ccw(c-4.954,-5) -4.954,-7.6 ; -6.904,5.01 -6.904,0.5 ccw(c-6.466,0.5) -6.776,0.19 -6.571,-0.015 -6.373,-0.212 cw(c-6.661,-0.5) -6.254,-0.5 -6.254,-5.007 ; -6.904,5 cw(c-4.954,5) -4.954,6.95 ; -6.904,-0.5 -6.904,-5.01 ; -6.904,-5 ccw(c-4.954,-5) -4.954,-6.95 ; -6.254,5.007 -6.254,0.5 ; -6.254,5 cw(c-4.954,5) -4.954,6.3 ; -6.254,-5 ccw(c-4.954,-5) -4.954,-6.3 ; -5.604,5.004 -5.604,0.5 -5.604,-0.5 -5.604,-5.004 ; -5.604,5 cw(c-4.954,5) -4.954,5.65 ; -5.604,-5 ccw(c-4.954,-5) -4.954,-5.65 4.954,-5.65 ccw(c4.954,-5) 5.604,-5 5.604,-0.486 cw(c6.011,-0.486) 5.724,-0.198 5.921,-0.001 6.126,0.204 ccw(c5.816,0.514) 6.254,0.514 6.254,5.027 ; -4.97,8.9 4.962,8.9 ; -4.968,8.25 4.96,8.25 ; -4.967,7.6 4.959,7.6 ; -4.966,-8.9 4.967,-8.9 ; -4.964,6.95 4.956,6.95 ; -4.964,-8.25 4.964,-8.25 ; -4.962,-7.6 4.963,-7.6 ; -4.961,6.3 4.953,6.3 ; -4.96,-6.95 4.961,-6.95 ; -4.958,5.65 4.95,5.65 cw(c4.95,5) 5.6,5 ; -4.956,-6.3 4.957,-6.3 ; 4.95,8.899 cw(c4.95,4.999) 8.85,4.999 ; 4.95,8.249 cw(c4.95,4.999) 8.2,4.999 ; 4.95,7.6 cw(c4.95,5) 7.55,5 ; 4.95,6.95 cw(c4.95,5) 6.9,5 ; 4.95,6.3 cw(c4.95,5) 6.25,5 ; 4.954,-6.3 ccw(c4.954,-5) 6.254,-5 ; 4.954,-6.95 ccw(c4.954,-5) 6.904,-5 ; 4.954,-7.6 ccw(c4.954,-5) 7.554,-5 ; 4.954,-8.249 ccw(c4.954,-4.999) 8.204,-4.999 8.204,-0.485 cw(c8.611,-0.485) 8.323,-0.198 8.521,0 8.726,0.205 ccw(c8.416,0.515) 8.854,0.515 8.854,5.027 ; 4.954,-8.899 ccw(c4.954,-4.999) 8.854,-4.999 ; 5.604,5.028 5.604,0.514 ; 6.254,-0.486 6.254,-4.999 ; 6.904,5.024 6.904,0.514 ; 6.904,-4.996 6.904,-0.486 cw(c7.311,-0.486) 7.024,-0.198 7.221,-0.001 7.426,0.204 ccw(c7.116,0.514) 7.554,0.514 7.554,5.02 ; 7.554,-0.486 7.554,-4.993 ; 8.204,5.028 8.204,0.515 ; 8.854,-0.485 8.854,-4.998
  Bottom Layer lines w0.325: -8.204,-0.5 cw(c-7.797,-0.5) -8.085,-0.212 -7.887,-0.015 -7.682,0.19 ccw(c-7.992,0.5) -7.554,0.5 ; -6.904,-0.5 cw(c-6.497,-0.5) -6.785,-0.212 -6.587,-0.015 -6.382,0.19 ccw(c-6.692,0.5) -6.254,0.5 ; 5.604,0.514 ccw(c6.042,0.514) 5.733,0.204 5.937,-0.001 6.135,-0.198 cw(c5.847,-0.486) 6.254,-0.486 ; 6.904,0.514 ccw(c7.342,0.514) 7.033,0.204 7.237,-0.001 7.435,-0.198 cw(c7.147,-0.486) 7.554,-0.486 ; 8.204,0.515 ccw(c8.642,0.515) 8.332,0.205 8.537,0 8.735,-0.198 cw(c8.447,-0.485) 8.854,-0.485
C&K-INTER-SERIE-PTS820-WITHOUT-PEGS-H=2.0 [mm]
  rect 0.95x1.4 smd: 1(-2.075,0) 2(2.075,0)
  rect 1.15x0.75 smd: GND(-1.575,-1.525) GND(-1.575,1.525) GND(1.575,-1.525) GND(1.575,1.525)
  silkscreen extent -0.7,-1.6 0.7,1.6, body extent -2.1,-1.6 2.1,1.6, height 2
CASTELLATED_VIA [mm]
  round 1 hole 1: 1(0,0)
  Multi-Layer region: 0,-0.8 1.1,-0.8 1.1,0.8 0,0.8
CASTELLATED_VIA_DRILL=0.6-PAD=1.1 [mm]
  round 0.61 hole 0.6: 1(0,0)
  Multi-Layer region: 0,-0.55 0.9,-0.55 0.9,0.55 0,0.55
CASTELLATED_VIA_Drill=0.6-Pad=1.1 [mm]
  round 0.61 hole 0.6: 1(0,0)
  Multi-Layer region: 0,-0.55 0.9,-0.55 0.9,0.55 0,0.55
COILCRAFT-SELF-SERIE-0402DF [mm]
  rrect15% 0.375x0.65 smd: 1(-0.487,0) 2(0.487,0)
  body extent -0.56,-0.33 0.56,0.33, height 0.66
EVERLIGHT-19-213 [mm]
  rrect15% 0.8x1 smd: A(0.7,0) K(-0.7,0)
  silkscreen extent -1.4,-0.4 -1.4,0.4, body extent -0.85,-0.45 0.85,0.45, height 0.6
LED-PACKAGE-PLCC-4 [mm]
  rect 1.5x0.9 smd: A1(-1.35,-0.75) A2(1.35,0.75) K1(1.35,-0.75) K2(-1.35,0.75)
  silkscreen extent -1.7,-1.75 2.25,1.5, body extent -1.75,-1.4 1.75,1.4, height 1.91
LITE-ON-SMD-CHIP-LED-TOP-VIEW-BICOLOR-0606 [mm]
  rect 0.65x0.85 smd: A1(-0.425,0.675) A2(0.425,0.675) K1(-0.425,-0.675) K2(0.425,-0.675)
  silkscreen extent -1.02,-1.38 1.02,0.9, body extent -0.8,-0.9 0.8,0.9, height 0.71
"LOGO FCC" [mm]
  silkscreen extent -3.89,-2.09 1.95,2.1
mire_optique_standard [mm]
  round 1.5 smd mask+0.5: 1(0,0)
  Top Layer keep-out circle w0.01: c0,0 r1.5
MOLEX-47590-0001 [mm]
  rrect15% 0.4x1.35 smd: 1(1.3,0) 2(0.65,0) 3(0,0) 4(-0.65,0) 5(-1.3,0)
  oval 1.05x1.25 hole 0.65 slot 0.85 at 90 deg: G1(-2.225,0.325) G2(2.225,0.325)
  oval 1x1.7 hole 0.6 slot 1.3 at 90 deg: G3(-4.175,-2.675) G4(4.175,-2.675)
  rrect0% 2.9x1.9 smd paste-0.2: G5(0,-2.675)
  Top Layer region: 3.3,-1.725 3.3,-3.625 4.675,-3.625 4.675,-1.725
  Top Layer region: -4.675,-1.725 -4.675,-3.625 -3.3,-3.625 -3.3,-1.725
  silkscreen extent -3.85,-1.4 3.85,0, body extent -4.32,-5.43 4.33,0.47, height 2.74
NDK-NX2016SA [mm]
  rrect15% 0.95x1.05 smd: 1(-0.625,0.775) 2(-0.625,-0.775) 3(0.625,-0.775) 4(0.625,0.775)
  silkscreen extent -1.4,-1.6 1.4,1.6, body extent -0.85,-1.05 0.85,1.05, height 0.5
NDK-NX3225GD [mm]
  rrect15% 1.7x2.7 smd: 1(-1.05,0) 2(1.05,0)
  silkscreen extent -2.2,-1.65 2.2,-0.95, body extent -1.65,-1.3 1.65,1.3, height 1
Net-Tie-WIDTH-0.10mm [mm]
  rect 0.1x0.3 smd paste-1 mask-1: 1(0,-0.25) 2(0,0.25)
  Top Layer region: -0.05,-0.35 0.05,-0.35 0.05,0.4 -0.05,0.4
Net-Tie-WIDTH-0.50mm [mm]
  rect 0.5x0.3 smd paste-1 mask-1: 1(0,-0.3) 2(0,0.3)
  Top Layer region: -0.25,-0.35 0.25,-0.35 0.25,0.4 -0.25,0.4
PADS-x2-CMS-2.0x3.2-PAS-2.54 [mm]
  rect 2x3.2 smd: 1(-1.27,0) 2(1.27,0)
  silkscreen extent -2.75,-2 2.75,2
PLAGE-CMS-DIAM-0.6mm [mm]
  round 0.6 smd paste-0.8: 1(0,0)
PLAGE-CMS-DIAM-0.8mm [mm]
  round 0.8 smd paste-0.8: 1(0,0)
SAMTEC-FTSH-107-01-X-DV-K [mm]
  rect 0.75x2.8 smd: 1(-3.81,-2.035) 2(-3.81,2.035) 3(-2.54,-2.035) 4(-2.54,2.035) 5(-1.27,-2.035) 6(-1.27,2.035) 7(0,-2.035) 8(0,2.035) 9(1.27,-2.035) 10(1.27,2.035) 11(2.54,-2.035) 12(2.54,2.035) 13(3.81,-2.035) 14(3.81,2.035)
  silkscreen extent -5.1,-2.7 4.6,1.8, body extent -4.44,-2.92 4.45,2.92, height 6.12
SAMTEC-SSW-1X2PTS-RA-THROUGH-HOLE [mm]
  round 1.6 hole 1: 1(-1.27,0) 2(1.27,0)
  silkscreen extent -2.92,-9.4 2.92,-1.52, body extent -2.79,-10.03 2.79,0.2, height 2.43
SAMTEC-SSW-1X9PTS-RA-THROUGH-HOLE#1 [mm]
  round 1.6 hole 1: 1(-10.16,0) 2(-7.62,0) 3(-5.08,0) 4(-2.54,0) 5(0,0) 6(2.54,0) 7(5.08,0) 8(7.62,0) 9(10.16,0)
  silkscreen extent -11.97,-9.38 11.81,-0.35, body extent -11.68,-10.03 11.68,0.2, height 2.43
SAMTEC-SSW-1X9PTS-RA-THROUGH-HOLE#2 [mm]
  oval 1.6x2.1 hole 1 slot 1.5 at 90 deg: 1(-10.16,0) 2(-7.62,0) 3(-5.08,0) 4(-2.54,0) 5(0,0) 6(2.54,0) 7(5.08,0) 8(7.62,0) 9(10.16,0)
  silkscreen extent -11.81,-7.99 11.81,-1.52, body extent -11.68,-10.03 11.68,0.2, height 2.43
SAMTEC-TSW-1X9PTS-NA-STYLE-08 [mm]
  oval 1.6x2.1 hole 1 slot 1.5 at 90 deg: 1(10.16,0) 2(7.62,0) 3(5.08,0) 4(2.54,0) 5(0,0) 6(-2.54,0) 7(-5.08,0) 8(-7.62,0) 9(-10.16,0)
  silkscreen extent -11.05,-1.52 11.15,-1.52, body extent -11.56,-9.91 11.43,0.32, height 2.55
SOD323 [mil]
  rect 35x41 smd: A(0,43) K(0,-43)
  silkscreen extent -30,-75 30,33, body extent -27,-51 27,51, height 43
SOT23-5PINS [mm]
  rect 0.635x1.041 smd: 1(0.95,1.17) 2(0,1.17) 3(-0.95,1.17) 4(-0.95,-1.17) 5(0.95,-1.17)
  silkscreen extent -1.54,-0.9 1.54,0.9, body extent -1.5,-1.25 1.5,1.25, height 1.11
SOT23-B-C-E [mil]
  rect 35x41 smd: B(37,40) C(0,-40) E(-37,40)
  silkscreen extent -62,-40 63,10, body extent -59,-59 59,59, height 51
SOT23-G-D-S [mil]
  rect 35x41 smd: D(0,-40) G(37,40) S(-37,40)
  silkscreen extent -62,-40 -28,10, body extent -59,-59 59,59, height 51
SOT323-BCE [mil]
  rect 24x36 smd: B(25.59,35.43) C(0,-35.43) E(-25.59,35.43)
  silkscreen extent -40,-43 45,7, body extent -43,-44 43,44, height 43
ST-DFN6-3X3 [mm]
  rrect15% 0.45x0.775 smd: 1(-0.95,-1.462) 2(0,-1.462) 3(0.95,-1.462) 4(0.95,1.462) 5(0,1.462) 6(-0.95,1.462)
  rect 2.5x1.5 smd paste-0.2 mask-0.15: 7(0,0)
  silkscreen extent -1.73,-2.16 1.58,1.55, body extent -1.55,-1.55 1.55,1.55, height 0.99
ST-LQFP48-PAS-0.5-7X7-H=1.6 [mm]
  rrect30% 1.45x0.3 smd: 1(-4.125,2.75) 2(-4.125,2.25) 3(-4.125,1.75) 4(-4.125,1.25) 5(-4.125,0.75) 6(-4.125,0.25) 7(-4.125,-0.25) 8(-4.125,-0.75) 9(-4.125,-1.25) 10(-4.125,-1.75) 11(-4.125,-2.25) 12(-4.125,-2.75) 25(4.125,-2.75) 26(4.125,-2.25) 27(4.125,-1.75) 28(4.125,-1.25) 29(4.125,-0.75) 30(4.125,-0.25) 31(4.125,0.25) 32(4.125,0.75) 33(4.125,1.25) 34(4.125,1.75) 35(4.125,2.25) 36(4.125,2.75)
  rrect30% 0.3x1.45 smd: 13(-2.75,-4.125) 14(-2.25,-4.125) 15(-1.75,-4.125) 16(-1.25,-4.125) 17(-0.75,-4.125) 18(-0.25,-4.125) 19(0.25,-4.125) 20(0.75,-4.125) 21(1.25,-4.125) 22(1.75,-4.125) 23(2.25,-4.125) 24(2.75,-4.125) 37(2.75,4.125) 38(2.25,4.125) 39(1.75,4.125) 40(1.25,4.125) 41(0.75,4.125) 42(0.25,4.125) 43(-0.25,4.125) 44(-0.75,4.125) 45(-1.25,4.125) 46(-1.75,4.125) 47(-2.25,4.125) 48(-2.75,4.125)
  silkscreen extent -5.2,-4.6 4.6,4.6, body extent -4.5,-4.5 4.5,4.5, height 1.6
ST-MICRO-QFN-8L-PKG-2.5x1.2-PAS-0.5 [mm]
  rect 0.85x0.25 smd: 1(-0.575,0.75) 2(-0.575,0.25) 3(-0.575,-0.25) 4(-0.575,-0.75) 5(0.575,-0.75) 6(0.575,-0.25) 7(0.575,0.25) 8(0.575,0.75)
  rect 0.35x0.475 smd: 1(-0.325,0.863) 4(-0.325,-0.863) 5(0.325,-0.863) 8(0.325,0.863)
  silkscreen extent -1.11,-1.4 0.65,1.4, body extent -0.65,-1.3 0.65,1.3, height 0.61
ST-PACKAGE-1610-2PINS-A-K [mm]
  rect 0.75x0.9 smd: A(0.675,0) K(-0.675,0)
  silkscreen extent -1.35,-0.7 0.9,0.92, body extent -0.85,-0.55 0.85,0.55, height 0.6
